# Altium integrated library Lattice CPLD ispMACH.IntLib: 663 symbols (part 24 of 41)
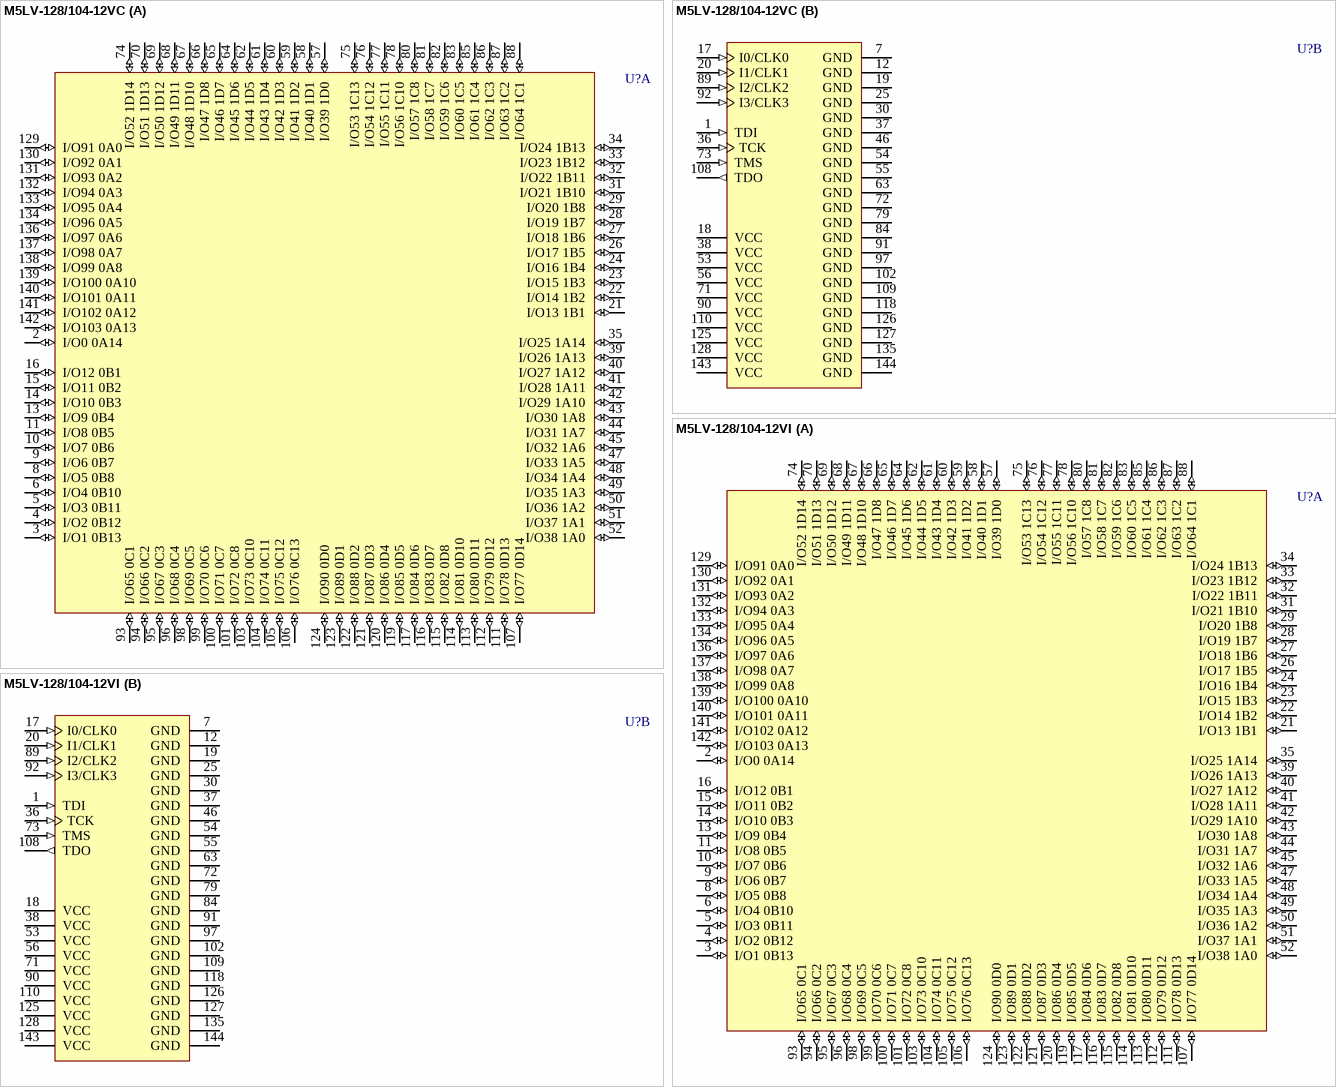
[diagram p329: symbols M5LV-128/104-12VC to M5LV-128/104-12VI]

## M5LV-128/104-12VI
designator U?
High-Density and High-I/O Complex PLD
footprint TQFP144_N (Thin QFP, 144-Leads, Body 20x20mm, Pitch 0.5mm, IPC Medium Density)
footprint TQFP144_L (Thin QFP, 144-Leads, Body 20x20mm, Pitch 0.5mm, IPC High Density)
footprint TQFP144_M (Thin QFP, 144-Leads, Body 20x20mm, Pitch 0.5mm, IPC Low Density)
3D model M5LV-TQFP144 (144-Pin Thin Quad Flat Pack (TQFP144))
part A pins: 2 I/O0 0A14 (io), 3 I/O1 0B13 (io), 4 I/O2 0B12 (io), 5 I/O3 0B11 (io), 6 I/O4 0B10 (io), 8 I/O5 0B8 (io), 9 I/O6 0B7 (io), 10 I/O7 0B6 (io), 11 I/O8 0B5 (io), 13 I/O9 0B4 (io), 14 I/O10 0B3 (io), 15 I/O11 0B2 (io), 16 I/O12 0B1 (io), 21 I/O13 1B1 (io), 22 I/O14 1B2 (io), 23 I/O15 1B3 (io), 24 I/O16 1B4 (io), 26 I/O17 1B5 (io), 27 I/O18 1B6 (io), 28 I/O19 1B7 (io), 29 I/O20 1B8 (io), 31 I/O21 1B10 (io), 32 I/O22 1B11 (io), 33 I/O23 1B12 (io), 34 I/O24 1B13 (io), 35 I/O25 1A14 (io), 39 I/O26 1A13 (io), 40 I/O27 1A12 (io), 41 I/O28 1A11 (io), 42 I/O29 1A10 (io), 43 I/O30 1A8 (io), 44 I/O31 1A7 (io), 45 I/O32 1A6 (io), 47 I/O33 1A5 (io), 48 I/O34 1A4 (io), 49 I/O35 1A3 (io), 50 I/O36 1A2 (io), 51 I/O37 1A1 (io), 52 I/O38 1A0 (io), 57 I/O39 1D0 (io), 58 I/O40 1D1 (io), 59 I/O41 1D2 (io), 60 I/O42 1D3 (io), 61 I/O43 1D4 (io), 62 I/O44 1D5 (io), 64 I/O45 1D6 (io), 65 I/O46 1D7 (io), 66 I/O47 1D8 (io), 67 I/O48 1D10 (io), 68 I/O49 1D11 (io), 69 I/O50 1D12 (io), 70 I/O51 1D13 (io), 74 I/O52 1D14 (io), 75 I/O53 1C13 (io), 76 I/O54 1C12 (io), 77 I/O55 1C11 (io), 78 I/O56 1C10 (io), 80 I/O57 1C8 (io), 81 I/O58 1C7 (io), 82 I/O59 1C6 (io), 83 I/O60 1C5 (io), 85 I/O61 1C4 (io), 86 I/O62 1C3 (io), 87 I/O63 1C2 (io), 88 I/O64 1C1 (io), 93 I/O65 0C1 (io), 94 I/O66 0C2 (io), 95 I/O67 0C3 (io), 96 I/O68 0C4 (io), 98 I/O69 0C5 (io), 99 I/O70 0C6 (io), 100 I/O71 0C7 (io), 101 I/O72 0C8 (io), 103 I/O73 0C10 (io), 104 I/O74 0C11 (io), 105 I/O75 0C12 (io), 106 I/O76 0C13 (io), 107 I/O77 0D14 (io), 111 I/O78 0D13 (io), 112 I/O79 0D12 (io), 113 I/O80 0D11 (io), 114 I/O81 0D10 (io), 115 I/O82 0D8 (io), 116 I/O83 0D7 (io), 117 I/O84 0D6 (io), 119 I/O85 0D5 (io), 120 I/O86 0D4 (io), 121 I/O87 0D3 (io), 122 I/O88 0D2 (io), 123 I/O89 0D1 (io), 124 I/O90 0D0 (io), 129 I/O91 0A0 (io), 130 I/O92 0A1 (io), 131 I/O93 0A2 (io), 132 I/O94 0A3 (io), 133 I/O95 0A4 (io), 134 I/O96 0A5 (io), 136 I/O97 0A6 (io), 137 I/O98 0A7 (io), 138 I/O99 0A8 (io), 139 I/O100 0A10 (io), 140 I/O101 0A11 (io), 141 I/O102 0A12 (io), 142 I/O103 0A13 (io)
part B pins: 1 TDI (in), 7 GND (power), 12 GND (power), 17 I0/CLK0 (in), 18 VCC (power), 19 GND (power), 20 I1/CLK1 (in), 25 GND (power), 30 GND (power), 36 TCK (in), 37 GND (power), 38 VCC (power), 46 GND (power), 53 VCC (power), 54 GND (power), 55 GND (power), 56 VCC (power), 63 GND (power), 71 VCC (power), 72 GND (power), 73 TMS (in), 79 GND (power), 84 GND (power), 89 I2/CLK2 (in), 90 VCC (power), 91 GND (power), 92 I3/CLK3 (in), 97 GND (power), 102 GND (power), 108 TDO (out), 109 GND (power), 110 VCC (power), 118 GND (power), 125 VCC (power), 126 GND (power), 127 GND (power), 128 VCC (power), 135 GND (power), 143 VCC (power), 144 GND (power)

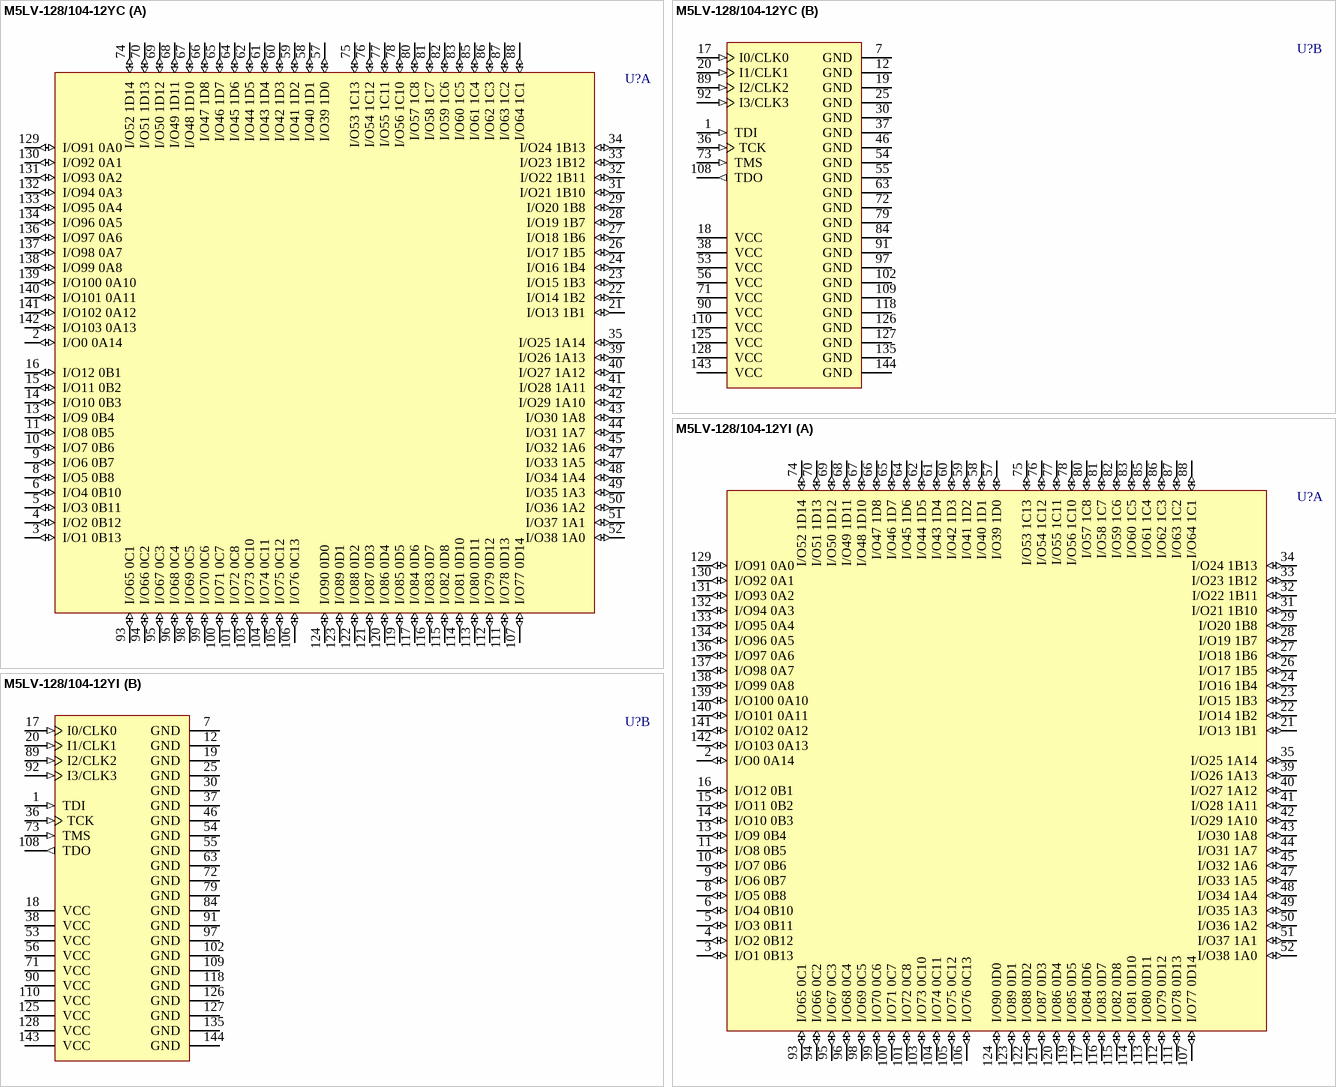
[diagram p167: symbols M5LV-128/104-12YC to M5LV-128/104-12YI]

## M5LV-128/104-12YC
designator U?
High-Density and High-I/O Complex PLD
footprint PQFP144_N (QFP, 144-Leads, Body 28 x 28mm, Pitch 0.65mm, IPC Medium Density)
footprint PQFP144_L (QFP, 144-Leads, Body 28 x 28mm, Pitch 0.65mm, IPC High Density)
footprint PQFP144_M (QFP, 144-Leads, Body 28 x 28mm, Pitch 0.65mm, IPC Low Density)
3D model M5LV-PQFP144 (144-Pin Quad Flat Pack 0.65 mm Pitch)
part A pins: 2 I/O0 0A14 (io), 3 I/O1 0B13 (io), 4 I/O2 0B12 (io), 5 I/O3 0B11 (io), 6 I/O4 0B10 (io), 8 I/O5 0B8 (io), 9 I/O6 0B7 (io), 10 I/O7 0B6 (io), 11 I/O8 0B5 (io), 13 I/O9 0B4 (io), 14 I/O10 0B3 (io), 15 I/O11 0B2 (io), 16 I/O12 0B1 (io), 21 I/O13 1B1 (io), 22 I/O14 1B2 (io), 23 I/O15 1B3 (io), 24 I/O16 1B4 (io), 26 I/O17 1B5 (io), 27 I/O18 1B6 (io), 28 I/O19 1B7 (io), 29 I/O20 1B8 (io), 31 I/O21 1B10 (io), 32 I/O22 1B11 (io), 33 I/O23 1B12 (io), 34 I/O24 1B13 (io), 35 I/O25 1A14 (io), 39 I/O26 1A13 (io), 40 I/O27 1A12 (io), 41 I/O28 1A11 (io), 42 I/O29 1A10 (io), 43 I/O30 1A8 (io), 44 I/O31 1A7 (io), 45 I/O32 1A6 (io), 47 I/O33 1A5 (io), 48 I/O34 1A4 (io), 49 I/O35 1A3 (io), 50 I/O36 1A2 (io), 51 I/O37 1A1 (io), 52 I/O38 1A0 (io), 57 I/O39 1D0 (io), 58 I/O40 1D1 (io), 59 I/O41 1D2 (io), 60 I/O42 1D3 (io), 61 I/O43 1D4 (io), 62 I/O44 1D5 (io), 64 I/O45 1D6 (io), 65 I/O46 1D7 (io), 66 I/O47 1D8 (io), 67 I/O48 1D10 (io), 68 I/O49 1D11 (io), 69 I/O50 1D12 (io), 70 I/O51 1D13 (io), 74 I/O52 1D14 (io), 75 I/O53 1C13 (io), 76 I/O54 1C12 (io), 77 I/O55 1C11 (io), 78 I/O56 1C10 (io), 80 I/O57 1C8 (io), 81 I/O58 1C7 (io), 82 I/O59 1C6 (io), 83 I/O60 1C5 (io), 85 I/O61 1C4 (io), 86 I/O62 1C3 (io), 87 I/O63 1C2 (io), 88 I/O64 1C1 (io), 93 I/O65 0C1 (io), 94 I/O66 0C2 (io), 95 I/O67 0C3 (io), 96 I/O68 0C4 (io), 98 I/O69 0C5 (io), 99 I/O70 0C6 (io), 100 I/O71 0C7 (io), 101 I/O72 0C8 (io), 103 I/O73 0C10 (io), 104 I/O74 0C11 (io), 105 I/O75 0C12 (io), 106 I/O76 0C13 (io), 107 I/O77 0D14 (io), 111 I/O78 0D13 (io), 112 I/O79 0D12 (io), 113 I/O80 0D11 (io), 114 I/O81 0D10 (io), 115 I/O82 0D8 (io), 116 I/O83 0D7 (io), 117 I/O84 0D6 (io), 119 I/O85 0D5 (io), 120 I/O86 0D4 (io), 121 I/O87 0D3 (io), 122 I/O88 0D2 (io), 123 I/O89 0D1 (io), 124 I/O90 0D0 (io), 129 I/O91 0A0 (io), 130 I/O92 0A1 (io), 131 I/O93 0A2 (io), 132 I/O94 0A3 (io), 133 I/O95 0A4 (io), 134 I/O96 0A5 (io), 136 I/O97 0A6 (io), 137 I/O98 0A7 (io), 138 I/O99 0A8 (io), 139 I/O100 0A10 (io), 140 I/O101 0A11 (io), 141 I/O102 0A12 (io), 142 I/O103 0A13 (io)
part B pins: 1 TDI (in), 7 GND (power), 12 GND (power), 17 I0/CLK0 (in), 18 VCC (power), 19 GND (power), 20 I1/CLK1 (in), 25 GND (power), 30 GND (power), 36 TCK (in), 37 GND (power), 38 VCC (power), 46 GND (power), 53 VCC (power), 54 GND (power), 55 GND (power), 56 VCC (power), 63 GND (power), 71 VCC (power), 72 GND (power), 73 TMS (in), 79 GND (power), 84 GND (power), 89 I2/CLK2 (in), 90 VCC (power), 91 GND (power), 92 I3/CLK3 (in), 97 GND (power), 102 GND (power), 108 TDO (out), 109 GND (power), 110 VCC (power), 118 GND (power), 125 VCC (power), 126 GND (power), 127 GND (power), 128 VCC (power), 135 GND (power), 143 VCC (power), 144 GND (power)

## M5LV-128/104-12YI
designator U?
High-Density and High-I/O Complex PLD
footprint PQFP144_N (QFP, 144-Leads, Body 28 x 28mm, Pitch 0.65mm, IPC Medium Density)
footprint PQFP144_L (QFP, 144-Leads, Body 28 x 28mm, Pitch 0.65mm, IPC High Density)
footprint PQFP144_M (QFP, 144-Leads, Body 28 x 28mm, Pitch 0.65mm, IPC Low Density)
3D model M5LV-PQFP144 (144-Pin Quad Flat Pack 0.65 mm Pitch)
part A pins: 2 I/O0 0A14 (io), 3 I/O1 0B13 (io), 4 I/O2 0B12 (io), 5 I/O3 0B11 (io), 6 I/O4 0B10 (io), 8 I/O5 0B8 (io), 9 I/O6 0B7 (io), 10 I/O7 0B6 (io), 11 I/O8 0B5 (io), 13 I/O9 0B4 (io), 14 I/O10 0B3 (io), 15 I/O11 0B2 (io), 16 I/O12 0B1 (io), 21 I/O13 1B1 (io), 22 I/O14 1B2 (io), 23 I/O15 1B3 (io), 24 I/O16 1B4 (io), 26 I/O17 1B5 (io), 27 I/O18 1B6 (io), 28 I/O19 1B7 (io), 29 I/O20 1B8 (io), 31 I/O21 1B10 (io), 32 I/O22 1B11 (io), 33 I/O23 1B12 (io), 34 I/O24 1B13 (io), 35 I/O25 1A14 (io), 39 I/O26 1A13 (io), 40 I/O27 1A12 (io), 41 I/O28 1A11 (io), 42 I/O29 1A10 (io), 43 I/O30 1A8 (io), 44 I/O31 1A7 (io), 45 I/O32 1A6 (io), 47 I/O33 1A5 (io), 48 I/O34 1A4 (io), 49 I/O35 1A3 (io), 50 I/O36 1A2 (io), 51 I/O37 1A1 (io), 52 I/O38 1A0 (io), 57 I/O39 1D0 (io), 58 I/O40 1D1 (io), 59 I/O41 1D2 (io), 60 I/O42 1D3 (io), 61 I/O43 1D4 (io), 62 I/O44 1D5 (io), 64 I/O45 1D6 (io), 65 I/O46 1D7 (io), 66 I/O47 1D8 (io), 67 I/O48 1D10 (io), 68 I/O49 1D11 (io), 69 I/O50 1D12 (io), 70 I/O51 1D13 (io), 74 I/O52 1D14 (io), 75 I/O53 1C13 (io), 76 I/O54 1C12 (io), 77 I/O55 1C11 (io), 78 I/O56 1C10 (io), 80 I/O57 1C8 (io), 81 I/O58 1C7 (io), 82 I/O59 1C6 (io), 83 I/O60 1C5 (io), 85 I/O61 1C4 (io), 86 I/O62 1C3 (io), 87 I/O63 1C2 (io), 88 I/O64 1C1 (io), 93 I/O65 0C1 (io), 94 I/O66 0C2 (io), 95 I/O67 0C3 (io), 96 I/O68 0C4 (io), 98 I/O69 0C5 (io), 99 I/O70 0C6 (io), 100 I/O71 0C7 (io), 101 I/O72 0C8 (io), 103 I/O73 0C10 (io), 104 I/O74 0C11 (io), 105 I/O75 0C12 (io), 106 I/O76 0C13 (io), 107 I/O77 0D14 (io), 111 I/O78 0D13 (io), 112 I/O79 0D12 (io), 113 I/O80 0D11 (io), 114 I/O81 0D10 (io), 115 I/O82 0D8 (io), 116 I/O83 0D7 (io), 117 I/O84 0D6 (io), 119 I/O85 0D5 (io), 120 I/O86 0D4 (io), 121 I/O87 0D3 (io), 122 I/O88 0D2 (io), 123 I/O89 0D1 (io), 124 I/O90 0D0 (io), 129 I/O91 0A0 (io), 130 I/O92 0A1 (io), 131 I/O93 0A2 (io), 132 I/O94 0A3 (io), 133 I/O95 0A4 (io), 134 I/O96 0A5 (io), 136 I/O97 0A6 (io), 137 I/O98 0A7 (io), 138 I/O99 0A8 (io), 139 I/O100 0A10 (io), 140 I/O101 0A11 (io), 141 I/O102 0A12 (io), 142 I/O103 0A13 (io)
part B pins: 1 TDI (in), 7 GND (power), 12 GND (power), 17 I0/CLK0 (in), 18 VCC (power), 19 GND (power), 20 I1/CLK1 (in), 25 GND (power), 30 GND (power), 36 TCK (in), 37 GND (power), 38 VCC (power), 46 GND (power), 53 VCC (power), 54 GND (power), 55 GND (power), 56 VCC (power), 63 GND (power), 71 VCC (power), 72 GND (power), 73 TMS (in), 79 GND (power), 84 GND (power), 89 I2/CLK2 (in), 90 VCC (power), 91 GND (power), 92 I3/CLK3 (in), 97 GND (power), 102 GND (power), 108 TDO (out), 109 GND (power), 110 VCC (power), 118 GND (power), 125 VCC (power), 126 GND (power), 127 GND (power), 128 VCC (power), 135 GND (power), 143 VCC (power), 144 GND (power)

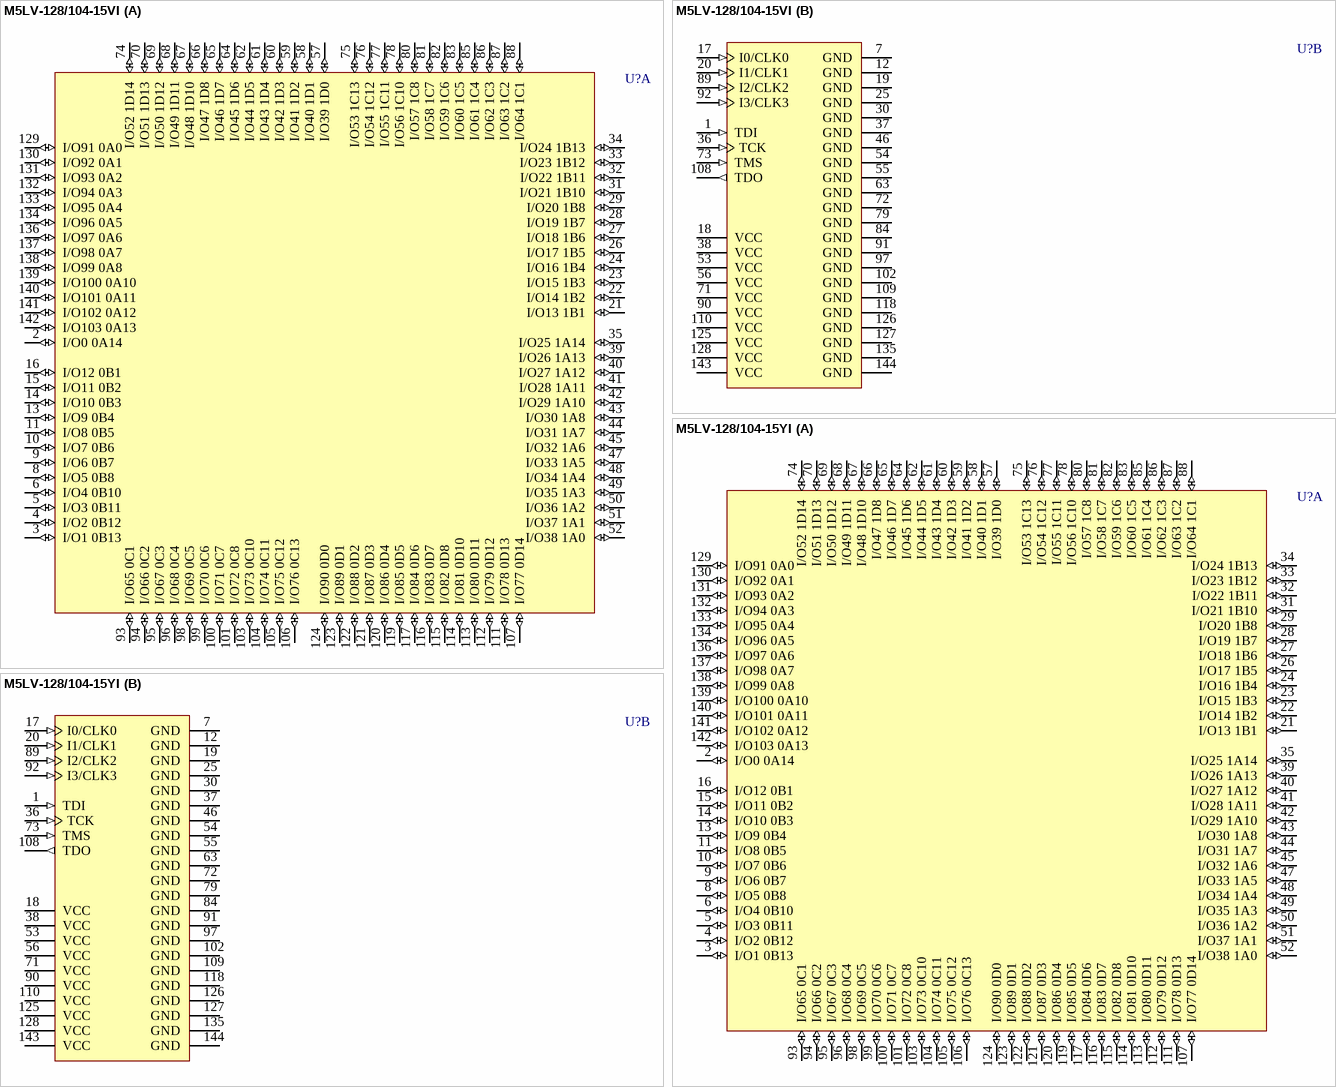
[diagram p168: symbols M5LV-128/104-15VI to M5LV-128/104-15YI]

## M5LV-128/104-15VI
designator U?
High-Density and High-I/O Complex PLD
footprint TQFP144_N (Thin QFP, 144-Leads, Body 20x20mm, Pitch 0.5mm, IPC Medium Density)
footprint TQFP144_L (Thin QFP, 144-Leads, Body 20x20mm, Pitch 0.5mm, IPC High Density)
footprint TQFP144_M (Thin QFP, 144-Leads, Body 20x20mm, Pitch 0.5mm, IPC Low Density)
3D model M5LV-TQFP144 (144-Pin Thin Quad Flat Pack (TQFP144))
part A pins: 2 I/O0 0A14 (io), 3 I/O1 0B13 (io), 4 I/O2 0B12 (io), 5 I/O3 0B11 (io), 6 I/O4 0B10 (io), 8 I/O5 0B8 (io), 9 I/O6 0B7 (io), 10 I/O7 0B6 (io), 11 I/O8 0B5 (io), 13 I/O9 0B4 (io), 14 I/O10 0B3 (io), 15 I/O11 0B2 (io), 16 I/O12 0B1 (io), 21 I/O13 1B1 (io), 22 I/O14 1B2 (io), 23 I/O15 1B3 (io), 24 I/O16 1B4 (io), 26 I/O17 1B5 (io), 27 I/O18 1B6 (io), 28 I/O19 1B7 (io), 29 I/O20 1B8 (io), 31 I/O21 1B10 (io), 32 I/O22 1B11 (io), 33 I/O23 1B12 (io), 34 I/O24 1B13 (io), 35 I/O25 1A14 (io), 39 I/O26 1A13 (io), 40 I/O27 1A12 (io), 41 I/O28 1A11 (io), 42 I/O29 1A10 (io), 43 I/O30 1A8 (io), 44 I/O31 1A7 (io), 45 I/O32 1A6 (io), 47 I/O33 1A5 (io), 48 I/O34 1A4 (io), 49 I/O35 1A3 (io), 50 I/O36 1A2 (io), 51 I/O37 1A1 (io), 52 I/O38 1A0 (io), 57 I/O39 1D0 (io), 58 I/O40 1D1 (io), 59 I/O41 1D2 (io), 60 I/O42 1D3 (io), 61 I/O43 1D4 (io), 62 I/O44 1D5 (io), 64 I/O45 1D6 (io), 65 I/O46 1D7 (io), 66 I/O47 1D8 (io), 67 I/O48 1D10 (io), 68 I/O49 1D11 (io), 69 I/O50 1D12 (io), 70 I/O51 1D13 (io), 74 I/O52 1D14 (io), 75 I/O53 1C13 (io), 76 I/O54 1C12 (io), 77 I/O55 1C11 (io), 78 I/O56 1C10 (io), 80 I/O57 1C8 (io), 81 I/O58 1C7 (io), 82 I/O59 1C6 (io), 83 I/O60 1C5 (io), 85 I/O61 1C4 (io), 86 I/O62 1C3 (io), 87 I/O63 1C2 (io), 88 I/O64 1C1 (io), 93 I/O65 0C1 (io), 94 I/O66 0C2 (io), 95 I/O67 0C3 (io), 96 I/O68 0C4 (io), 98 I/O69 0C5 (io), 99 I/O70 0C6 (io), 100 I/O71 0C7 (io), 101 I/O72 0C8 (io), 103 I/O73 0C10 (io), 104 I/O74 0C11 (io), 105 I/O75 0C12 (io), 106 I/O76 0C13 (io), 107 I/O77 0D14 (io), 111 I/O78 0D13 (io), 112 I/O79 0D12 (io), 113 I/O80 0D11 (io), 114 I/O81 0D10 (io), 115 I/O82 0D8 (io), 116 I/O83 0D7 (io), 117 I/O84 0D6 (io), 119 I/O85 0D5 (io), 120 I/O86 0D4 (io), 121 I/O87 0D3 (io), 122 I/O88 0D2 (io), 123 I/O89 0D1 (io), 124 I/O90 0D0 (io), 129 I/O91 0A0 (io), 130 I/O92 0A1 (io), 131 I/O93 0A2 (io), 132 I/O94 0A3 (io), 133 I/O95 0A4 (io), 134 I/O96 0A5 (io), 136 I/O97 0A6 (io), 137 I/O98 0A7 (io), 138 I/O99 0A8 (io), 139 I/O100 0A10 (io), 140 I/O101 0A11 (io), 141 I/O102 0A12 (io), 142 I/O103 0A13 (io)
part B pins: 1 TDI (in), 7 GND (power), 12 GND (power), 17 I0/CLK0 (in), 18 VCC (power), 19 GND (power), 20 I1/CLK1 (in), 25 GND (power), 30 GND (power), 36 TCK (in), 37 GND (power), 38 VCC (power), 46 GND (power), 53 VCC (power), 54 GND (power), 55 GND (power), 56 VCC (power), 63 GND (power), 71 VCC (power), 72 GND (power), 73 TMS (in), 79 GND (power), 84 GND (power), 89 I2/CLK2 (in), 90 VCC (power), 91 GND (power), 92 I3/CLK3 (in), 97 GND (power), 102 GND (power), 108 TDO (out), 109 GND (power), 110 VCC (power), 118 GND (power), 125 VCC (power), 126 GND (power), 127 GND (power), 128 VCC (power), 135 GND (power), 143 VCC (power), 144 GND (power)

## M5LV-128/104-15YI
designator U?
High-Density and High-I/O Complex PLD
footprint PQFP144_N (QFP, 144-Leads, Body 28 x 28mm, Pitch 0.65mm, IPC Medium Density)
footprint PQFP144_L (QFP, 144-Leads, Body 28 x 28mm, Pitch 0.65mm, IPC High Density)
footprint PQFP144_M (QFP, 144-Leads, Body 28 x 28mm, Pitch 0.65mm, IPC Low Density)
3D model M5LV-PQFP144 (144-Pin Quad Flat Pack 0.65 mm Pitch)
part A pins: 2 I/O0 0A14 (io), 3 I/O1 0B13 (io), 4 I/O2 0B12 (io), 5 I/O3 0B11 (io), 6 I/O4 0B10 (io), 8 I/O5 0B8 (io), 9 I/O6 0B7 (io), 10 I/O7 0B6 (io), 11 I/O8 0B5 (io), 13 I/O9 0B4 (io), 14 I/O10 0B3 (io), 15 I/O11 0B2 (io), 16 I/O12 0B1 (io), 21 I/O13 1B1 (io), 22 I/O14 1B2 (io), 23 I/O15 1B3 (io), 24 I/O16 1B4 (io), 26 I/O17 1B5 (io), 27 I/O18 1B6 (io), 28 I/O19 1B7 (io), 29 I/O20 1B8 (io), 31 I/O21 1B10 (io), 32 I/O22 1B11 (io), 33 I/O23 1B12 (io), 34 I/O24 1B13 (io), 35 I/O25 1A14 (io), 39 I/O26 1A13 (io), 40 I/O27 1A12 (io), 41 I/O28 1A11 (io), 42 I/O29 1A10 (io), 43 I/O30 1A8 (io), 44 I/O31 1A7 (io), 45 I/O32 1A6 (io), 47 I/O33 1A5 (io), 48 I/O34 1A4 (io), 49 I/O35 1A3 (io), 50 I/O36 1A2 (io), 51 I/O37 1A1 (io), 52 I/O38 1A0 (io), 57 I/O39 1D0 (io), 58 I/O40 1D1 (io), 59 I/O41 1D2 (io), 60 I/O42 1D3 (io), 61 I/O43 1D4 (io), 62 I/O44 1D5 (io), 64 I/O45 1D6 (io), 65 I/O46 1D7 (io), 66 I/O47 1D8 (io), 67 I/O48 1D10 (io), 68 I/O49 1D11 (io), 69 I/O50 1D12 (io), 70 I/O51 1D13 (io), 74 I/O52 1D14 (io), 75 I/O53 1C13 (io), 76 I/O54 1C12 (io), 77 I/O55 1C11 (io), 78 I/O56 1C10 (io), 80 I/O57 1C8 (io), 81 I/O58 1C7 (io), 82 I/O59 1C6 (io), 83 I/O60 1C5 (io), 85 I/O61 1C4 (io), 86 I/O62 1C3 (io), 87 I/O63 1C2 (io), 88 I/O64 1C1 (io), 93 I/O65 0C1 (io), 94 I/O66 0C2 (io), 95 I/O67 0C3 (io), 96 I/O68 0C4 (io), 98 I/O69 0C5 (io), 99 I/O70 0C6 (io), 100 I/O71 0C7 (io), 101 I/O72 0C8 (io), 103 I/O73 0C10 (io), 104 I/O74 0C11 (io), 105 I/O75 0C12 (io), 106 I/O76 0C13 (io), 107 I/O77 0D14 (io), 111 I/O78 0D13 (io), 112 I/O79 0D12 (io), 113 I/O80 0D11 (io), 114 I/O81 0D10 (io), 115 I/O82 0D8 (io), 116 I/O83 0D7 (io), 117 I/O84 0D6 (io), 119 I/O85 0D5 (io), 120 I/O86 0D4 (io), 121 I/O87 0D3 (io), 122 I/O88 0D2 (io), 123 I/O89 0D1 (io), 124 I/O90 0D0 (io), 129 I/O91 0A0 (io), 130 I/O92 0A1 (io), 131 I/O93 0A2 (io), 132 I/O94 0A3 (io), 133 I/O95 0A4 (io), 134 I/O96 0A5 (io), 136 I/O97 0A6 (io), 137 I/O98 0A7 (io), 138 I/O99 0A8 (io), 139 I/O100 0A10 (io), 140 I/O101 0A11 (io), 141 I/O102 0A12 (io), 142 I/O103 0A13 (io)
part B pins: 1 TDI (in), 7 GND (power), 12 GND (power), 17 I0/CLK0 (in), 18 VCC (power), 19 GND (power), 20 I1/CLK1 (in), 25 GND (power), 30 GND (power), 36 TCK (in), 37 GND (power), 38 VCC (power), 46 GND (power), 53 VCC (power), 54 GND (power), 55 GND (power), 56 VCC (power), 63 GND (power), 71 VCC (power), 72 GND (power), 73 TMS (in), 79 GND (power), 84 GND (power), 89 I2/CLK2 (in), 90 VCC (power), 91 GND (power), 92 I3/CLK3 (in), 97 GND (power), 102 GND (power), 108 TDO (out), 109 GND (power), 110 VCC (power), 118 GND (power), 125 VCC (power), 126 GND (power), 127 GND (power), 128 VCC (power), 135 GND (power), 143 VCC (power), 144 GND (power)

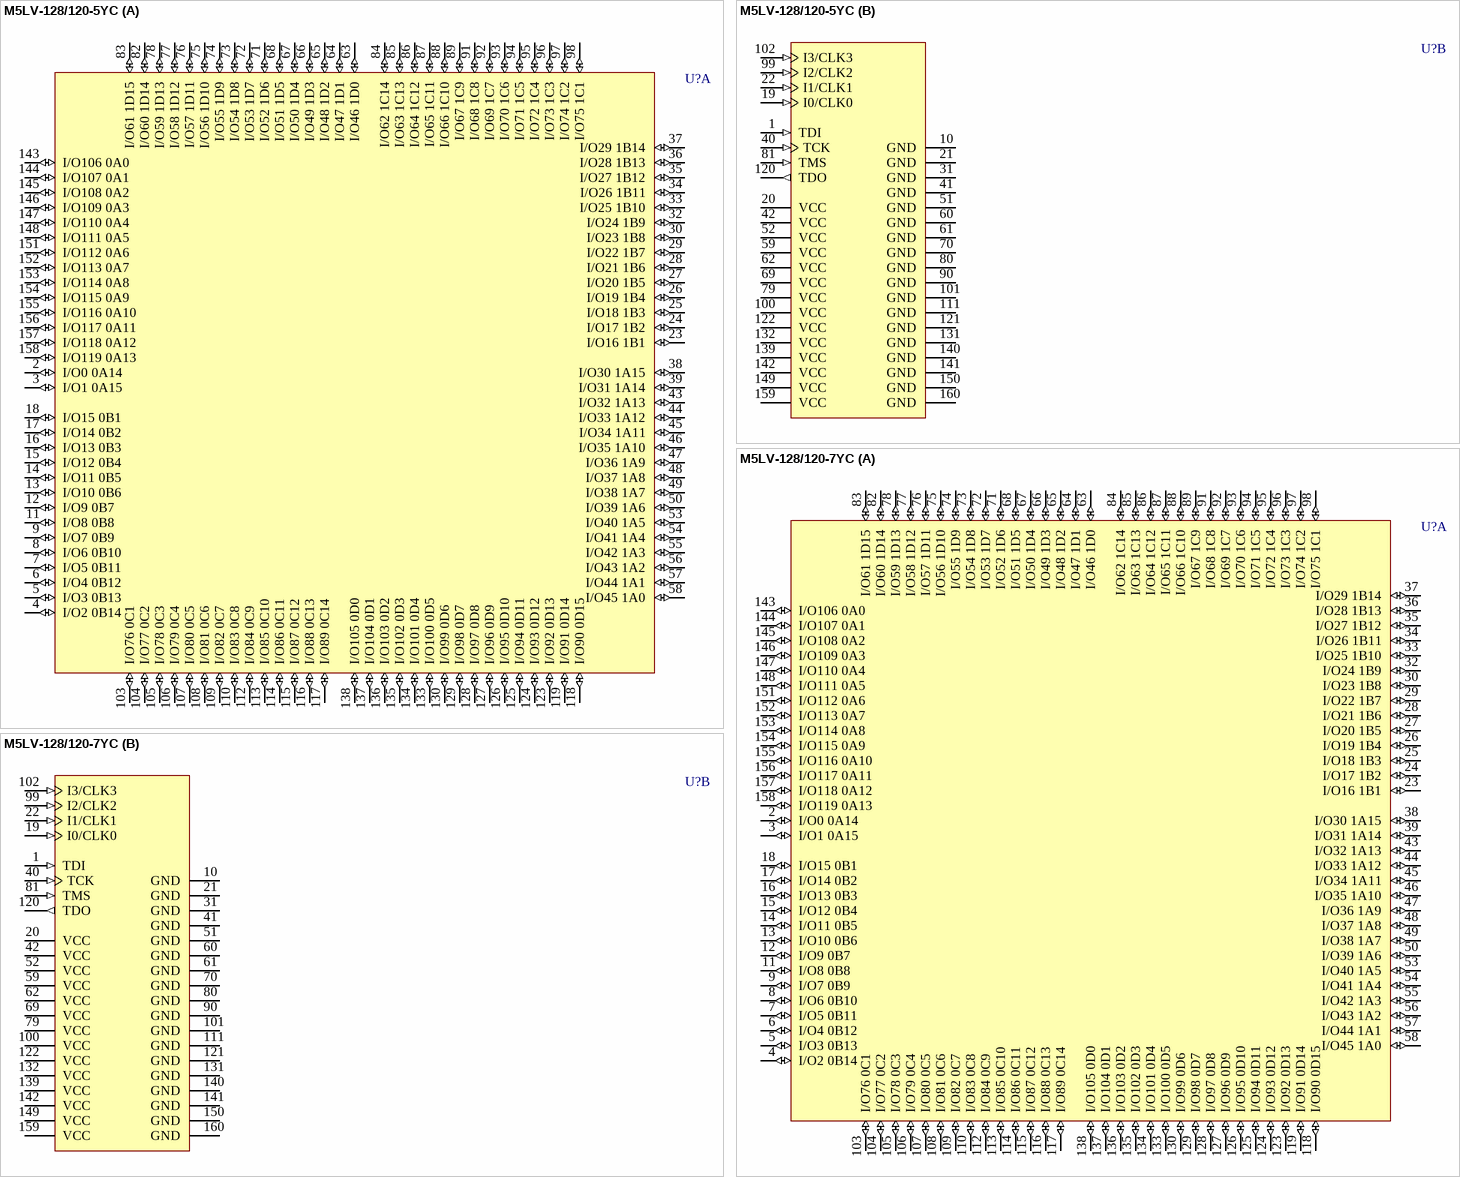
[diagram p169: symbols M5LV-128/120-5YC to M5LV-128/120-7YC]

## M5LV-128/120-5YC
designator U?
High-Density and High-I/O Complex PLD
footprint PQFP160_N (QFP, 160-Leads, Body 28 x 28mm, Pitch 0.65mm, IPC Medium Density)
footprint PQFP160_L (QFP, 160-Leads, Body 28 x 28mm, Pitch 0.65mm, IPC High Density)
footprint PQFP160_M (QFP, 160-Leads, Body 28 x 28mm, Pitch 0.65mm, IPC Low Density)
3D model M5LV-PQFP160 (160-Pin Quad Flat Pack 0.65 mm Pitch)
part A pins: 2 I/O0 0A14 (io), 3 I/O1 0A15 (io), 4 I/O2 0B14 (io), 5 I/O3 0B13 (io), 6 I/O4 0B12 (io), 7 I/O5 0B11 (io), 8 I/O6 0B10 (io), 9 I/O7 0B9 (io), 11 I/O8 0B8 (io), 12 I/O9 0B7 (io), 13 I/O10 0B6 (io), 14 I/O11 0B5 (io), 15 I/O12 0B4 (io), 16 I/O13 0B3 (io), 17 I/O14 0B2 (io), 18 I/O15 0B1 (io), 23 I/O16 1B1 (io), 24 I/O17 1B2 (io), 25 I/O18 1B3 (io), 26 I/O19 1B4 (io), 27 I/O20 1B5 (io), 28 I/O21 1B6 (io), 29 I/O22 1B7 (io), 30 I/O23 1B8 (io), 32 I/O24 1B9 (io), 33 I/O25 1B10 (io), 34 I/O26 1B11 (io), 35 I/O27 1B12 (io), 36 I/O28 1B13 (io), 37 I/O29 1B14 (io), 38 I/O30 1A15 (io), 39 I/O31 1A14 (io), 43 I/O32 1A13 (io), 44 I/O33 1A12 (io), 45 I/O34 1A11 (io), 46 I/O35 1A10 (io), 47 I/O36 1A9 (io), 48 I/O37 1A8 (io), 49 I/O38 1A7 (io), 50 I/O39 1A6 (io), 53 I/O40 1A5 (io), 54 I/O41 1A4 (io), 55 I/O42 1A3 (io), 56 I/O43 1A2 (io), 57 I/O44 1A1 (io), 58 I/O45 1A0 (io), 63 I/O46 1D0 (io), 64 I/O47 1D1 (io), 65 I/O48 1D2 (io), 66 I/O49 1D3 (io), 67 I/O50 1D4 (io), 68 I/O51 1D5 (io), 71 I/O52 1D6 (io), 72 I/O53 1D7 (io), 73 I/O54 1D8 (io), 74 I/O55 1D9 (io), 75 I/O56 1D10 (io), 76 I/O57 1D11 (io), 77 I/O58 1D12 (io), 78 I/O59 1D13 (io), 82 I/O60 1D14 (io), 83 I/O61 1D15 (io), 84 I/O62 1C14 (io), 85 I/O63 1C13 (io), 86 I/O64 1C12 (io), 87 I/O65 1C11 (io), 88 I/O66 1C10 (io), 89 I/O67 1C9 (io), 91 I/O68 1C8 (io), 92 I/O69 1C7 (io), 93 I/O70 1C6 (io), 94 I/O71 1C5 (io), 95 I/O72 1C4 (io), 96 I/O73 1C3 (io), 97 I/O74 1C2 (io), 98 I/O75 1C1 (io), 103 I/O76 0C1 (io), 104 I/O77 0C2 (io), 105 I/O78 0C3 (io), 106 I/O79 0C4 (io), 107 I/O80 0C5 (io), 108 I/O81 0C6 (io), 109 I/O82 0C7 (io), 110 I/O83 0C8 (io), 112 I/O84 0C9 (io), 113 I/O85 0C10 (io), 114 I/O86 0C11 (io), 115 I/O87 0C12 (io), 116 I/O88 0C13 (io), 117 I/O89 0C14 (io), 118 I/O90 0D15 (io), 119 I/O91 0D14 (io), 123 I/O92 0D13 (io), 124 I/O93 0D12 (io), 125 I/O94 0D11 (io), 126 I/O95 0D10 (io), 127 I/O96 0D9 (io), 128 I/O97 0D8 (io), 129 I/O98 0D7 (io), 130 I/O99 0D6 (io), 133 I/O100 0D5 (io), 134 I/O101 0D4 (io), 135 I/O102 0D3 (io), 136 I/O103 0D2 (io), 137 I/O104 0D1 (io), 138 I/O105 0D0 (io), 143 I/O106 0A0 (io), 144 I/O107 0A1 (io), 145 I/O108 0A2 (io), 146 I/O109 0A3 (io), 147 I/O110 0A4 (io), 148 I/O111 0A5 (io), 151 I/O112 0A6 (io), 152 I/O113 0A7 (io), 153 I/O114 0A8 (io), 154 I/O115 0A9 (io), 155 I/O116 0A10 (io), 156 I/O117 0A11 (io), 157 I/O118 0A12 (io), 158 I/O119 0A13 (io)
part B pins: 1 TDI (in), 10 GND (power), 19 I0/CLK0 (in), 20 VCC (power), 21 GND (power), 22 I1/CLK1 (in), 31 GND (power), 40 TCK (in), 41 GND (power), 42 VCC (power), 51 GND (power), 52 VCC (power), 59 VCC (power), 60 GND (power), 61 GND (power), 62 VCC (power), 69 VCC (power), 70 GND (power), 79 VCC (power), 80 GND (power), 81 TMS (in), 90 GND (power), 99 I2/CLK2 (in), 100 VCC (power), 101 GND (power), 102 I3/CLK3 (in), 111 GND (power), 120 TDO (out), 121 GND (power), 122 VCC (power), 131 GND (power), 132 VCC (power), 139 VCC (power), 140 GND (power), 141 GND (power), 142 VCC (power), 149 VCC (power), 150 GND (power), 159 VCC (power), 160 GND (power)

## M5LV-128/120-7YC
designator U?
High-Density and High-I/O Complex PLD
footprint PQFP160_N (QFP, 160-Leads, Body 28 x 28mm, Pitch 0.65mm, IPC Medium Density)
footprint PQFP160_L (QFP, 160-Leads, Body 28 x 28mm, Pitch 0.65mm, IPC High Density)
footprint PQFP160_M (QFP, 160-Leads, Body 28 x 28mm, Pitch 0.65mm, IPC Low Density)
3D model M5LV-PQFP160 (160-Pin Quad Flat Pack 0.65 mm Pitch)
part A pins: 2 I/O0 0A14 (io), 3 I/O1 0A15 (io), 4 I/O2 0B14 (io), 5 I/O3 0B13 (io), 6 I/O4 0B12 (io), 7 I/O5 0B11 (io), 8 I/O6 0B10 (io), 9 I/O7 0B9 (io), 11 I/O8 0B8 (io), 12 I/O9 0B7 (io), 13 I/O10 0B6 (io), 14 I/O11 0B5 (io), 15 I/O12 0B4 (io), 16 I/O13 0B3 (io), 17 I/O14 0B2 (io), 18 I/O15 0B1 (io), 23 I/O16 1B1 (io), 24 I/O17 1B2 (io), 25 I/O18 1B3 (io), 26 I/O19 1B4 (io), 27 I/O20 1B5 (io), 28 I/O21 1B6 (io), 29 I/O22 1B7 (io), 30 I/O23 1B8 (io), 32 I/O24 1B9 (io), 33 I/O25 1B10 (io), 34 I/O26 1B11 (io), 35 I/O27 1B12 (io), 36 I/O28 1B13 (io), 37 I/O29 1B14 (io), 38 I/O30 1A15 (io), 39 I/O31 1A14 (io), 43 I/O32 1A13 (io), 44 I/O33 1A12 (io), 45 I/O34 1A11 (io), 46 I/O35 1A10 (io), 47 I/O36 1A9 (io), 48 I/O37 1A8 (io), 49 I/O38 1A7 (io), 50 I/O39 1A6 (io), 53 I/O40 1A5 (io), 54 I/O41 1A4 (io), 55 I/O42 1A3 (io), 56 I/O43 1A2 (io), 57 I/O44 1A1 (io), 58 I/O45 1A0 (io), 63 I/O46 1D0 (io), 64 I/O47 1D1 (io), 65 I/O48 1D2 (io), 66 I/O49 1D3 (io), 67 I/O50 1D4 (io), 68 I/O51 1D5 (io), 71 I/O52 1D6 (io), 72 I/O53 1D7 (io), 73 I/O54 1D8 (io), 74 I/O55 1D9 (io), 75 I/O56 1D10 (io), 76 I/O57 1D11 (io), 77 I/O58 1D12 (io), 78 I/O59 1D13 (io), 82 I/O60 1D14 (io), 83 I/O61 1D15 (io), 84 I/O62 1C14 (io), 85 I/O63 1C13 (io), 86 I/O64 1C12 (io), 87 I/O65 1C11 (io), 88 I/O66 1C10 (io), 89 I/O67 1C9 (io), 91 I/O68 1C8 (io), 92 I/O69 1C7 (io), 93 I/O70 1C6 (io), 94 I/O71 1C5 (io), 95 I/O72 1C4 (io), 96 I/O73 1C3 (io), 97 I/O74 1C2 (io), 98 I/O75 1C1 (io), 103 I/O76 0C1 (io), 104 I/O77 0C2 (io), 105 I/O78 0C3 (io), 106 I/O79 0C4 (io), 107 I/O80 0C5 (io), 108 I/O81 0C6 (io), 109 I/O82 0C7 (io), 110 I/O83 0C8 (io), 112 I/O84 0C9 (io), 113 I/O85 0C10 (io), 114 I/O86 0C11 (io), 115 I/O87 0C12 (io), 116 I/O88 0C13 (io), 117 I/O89 0C14 (io), 118 I/O90 0D15 (io), 119 I/O91 0D14 (io), 123 I/O92 0D13 (io), 124 I/O93 0D12 (io), 125 I/O94 0D11 (io), 126 I/O95 0D10 (io), 127 I/O96 0D9 (io), 128 I/O97 0D8 (io), 129 I/O98 0D7 (io), 130 I/O99 0D6 (io), 133 I/O100 0D5 (io), 134 I/O101 0D4 (io), 135 I/O102 0D3 (io), 136 I/O103 0D2 (io), 137 I/O104 0D1 (io), 138 I/O105 0D0 (io), 143 I/O106 0A0 (io), 144 I/O107 0A1 (io), 145 I/O108 0A2 (io), 146 I/O109 0A3 (io), 147 I/O110 0A4 (io), 148 I/O111 0A5 (io), 151 I/O112 0A6 (io), 152 I/O113 0A7 (io), 153 I/O114 0A8 (io), 154 I/O115 0A9 (io), 155 I/O116 0A10 (io), 156 I/O117 0A11 (io), 157 I/O118 0A12 (io), 158 I/O119 0A13 (io)
part B pins: 1 TDI (in), 10 GND (power), 19 I0/CLK0 (in), 20 VCC (power), 21 GND (power), 22 I1/CLK1 (in), 31 GND (power), 40 TCK (in), 41 GND (power), 42 VCC (power), 51 GND (power), 52 VCC (power), 59 VCC (power), 60 GND (power), 61 GND (power), 62 VCC (power), 69 VCC (power), 70 GND (power), 79 VCC (power), 80 GND (power), 81 TMS (in), 90 GND (power), 99 I2/CLK2 (in), 100 VCC (power), 101 GND (power), 102 I3/CLK3 (in), 111 GND (power), 120 TDO (out), 121 GND (power), 122 VCC (power), 131 GND (power), 132 VCC (power), 139 VCC (power), 140 GND (power), 141 GND (power), 142 VCC (power), 149 VCC (power), 150 GND (power), 159 VCC (power), 160 GND (power)

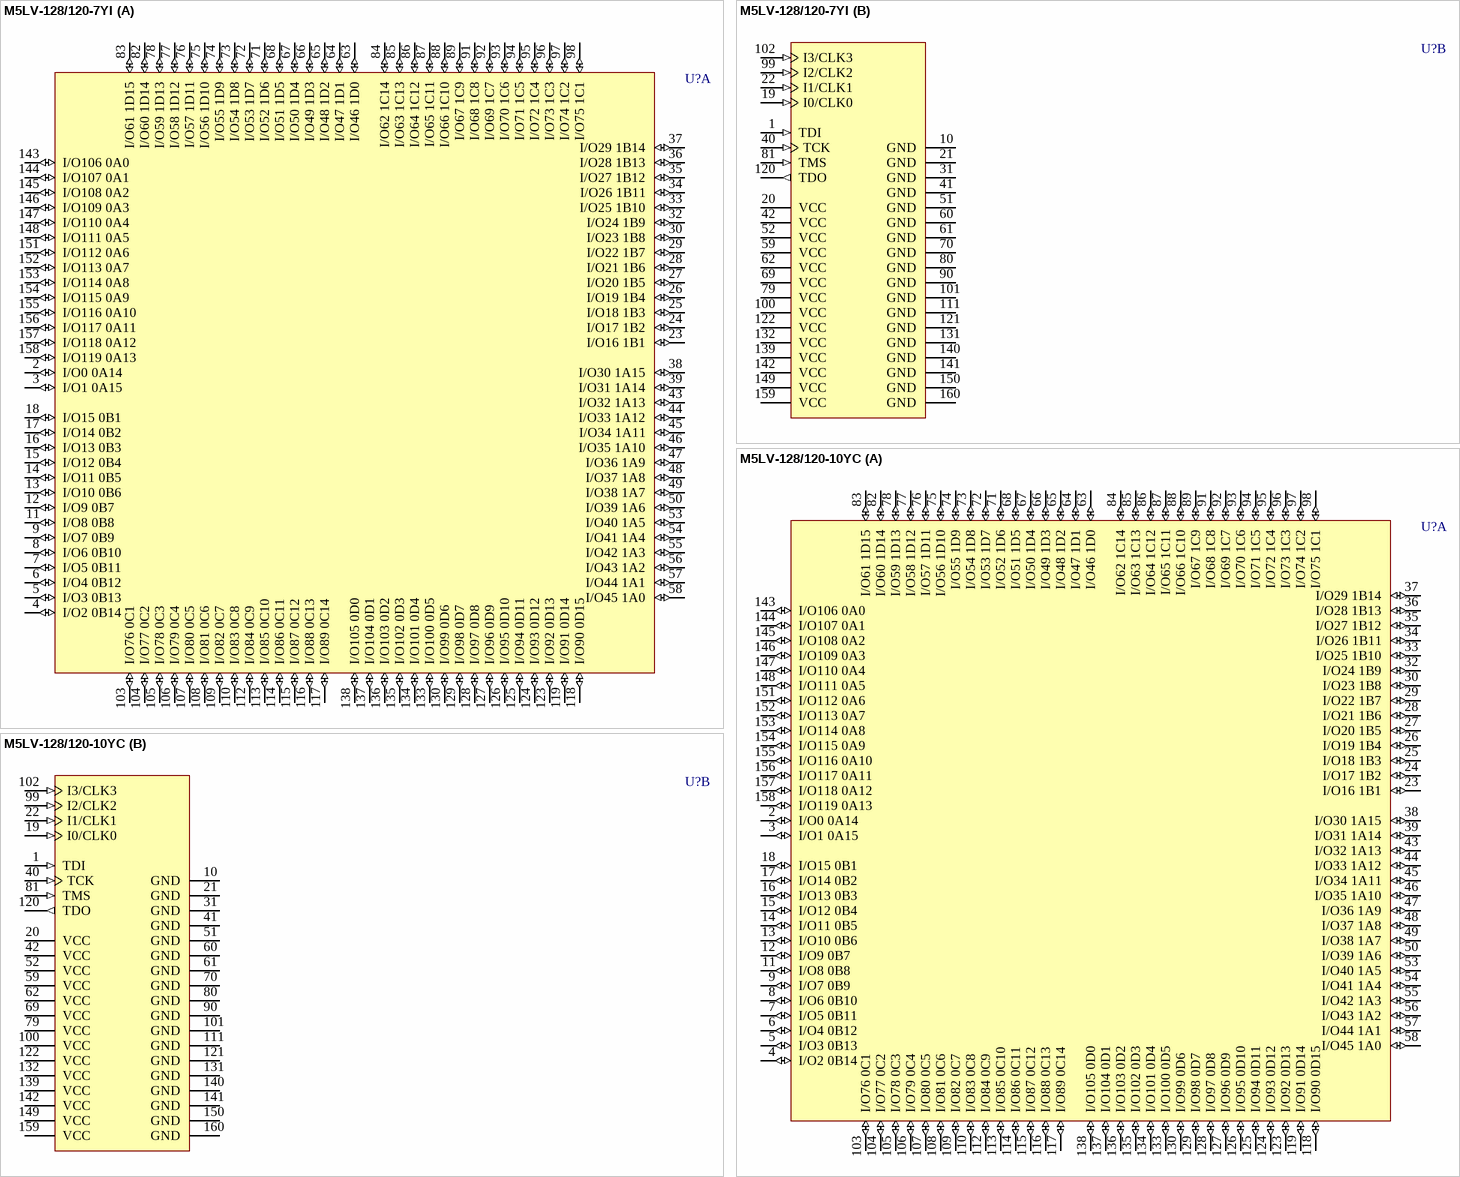
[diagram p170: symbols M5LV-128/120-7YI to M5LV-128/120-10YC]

## M5LV-128/120-7YI
designator U?
High-Density and High-I/O Complex PLD
footprint PQFP160_N (QFP, 160-Leads, Body 28 x 28mm, Pitch 0.65mm, IPC Medium Density)
footprint PQFP160_L (QFP, 160-Leads, Body 28 x 28mm, Pitch 0.65mm, IPC High Density)
footprint PQFP160_M (QFP, 160-Leads, Body 28 x 28mm, Pitch 0.65mm, IPC Low Density)
3D model M5LV-PQFP160 (160-Pin Quad Flat Pack 0.65 mm Pitch)
part A pins: 2 I/O0 0A14 (io), 3 I/O1 0A15 (io), 4 I/O2 0B14 (io), 5 I/O3 0B13 (io), 6 I/O4 0B12 (io), 7 I/O5 0B11 (io), 8 I/O6 0B10 (io), 9 I/O7 0B9 (io), 11 I/O8 0B8 (io), 12 I/O9 0B7 (io), 13 I/O10 0B6 (io), 14 I/O11 0B5 (io), 15 I/O12 0B4 (io), 16 I/O13 0B3 (io), 17 I/O14 0B2 (io), 18 I/O15 0B1 (io), 23 I/O16 1B1 (io), 24 I/O17 1B2 (io), 25 I/O18 1B3 (io), 26 I/O19 1B4 (io), 27 I/O20 1B5 (io), 28 I/O21 1B6 (io), 29 I/O22 1B7 (io), 30 I/O23 1B8 (io), 32 I/O24 1B9 (io), 33 I/O25 1B10 (io), 34 I/O26 1B11 (io), 35 I/O27 1B12 (io), 36 I/O28 1B13 (io), 37 I/O29 1B14 (io), 38 I/O30 1A15 (io), 39 I/O31 1A14 (io), 43 I/O32 1A13 (io), 44 I/O33 1A12 (io), 45 I/O34 1A11 (io), 46 I/O35 1A10 (io), 47 I/O36 1A9 (io), 48 I/O37 1A8 (io), 49 I/O38 1A7 (io), 50 I/O39 1A6 (io), 53 I/O40 1A5 (io), 54 I/O41 1A4 (io), 55 I/O42 1A3 (io), 56 I/O43 1A2 (io), 57 I/O44 1A1 (io), 58 I/O45 1A0 (io), 63 I/O46 1D0 (io), 64 I/O47 1D1 (io), 65 I/O48 1D2 (io), 66 I/O49 1D3 (io), 67 I/O50 1D4 (io), 68 I/O51 1D5 (io), 71 I/O52 1D6 (io), 72 I/O53 1D7 (io), 73 I/O54 1D8 (io), 74 I/O55 1D9 (io), 75 I/O56 1D10 (io), 76 I/O57 1D11 (io), 77 I/O58 1D12 (io), 78 I/O59 1D13 (io), 82 I/O60 1D14 (io), 83 I/O61 1D15 (io), 84 I/O62 1C14 (io), 85 I/O63 1C13 (io), 86 I/O64 1C12 (io), 87 I/O65 1C11 (io), 88 I/O66 1C10 (io), 89 I/O67 1C9 (io), 91 I/O68 1C8 (io), 92 I/O69 1C7 (io), 93 I/O70 1C6 (io), 94 I/O71 1C5 (io), 95 I/O72 1C4 (io), 96 I/O73 1C3 (io), 97 I/O74 1C2 (io), 98 I/O75 1C1 (io), 103 I/O76 0C1 (io), 104 I/O77 0C2 (io), 105 I/O78 0C3 (io), 106 I/O79 0C4 (io), 107 I/O80 0C5 (io), 108 I/O81 0C6 (io), 109 I/O82 0C7 (io), 110 I/O83 0C8 (io), 112 I/O84 0C9 (io), 113 I/O85 0C10 (io), 114 I/O86 0C11 (io), 115 I/O87 0C12 (io), 116 I/O88 0C13 (io), 117 I/O89 0C14 (io), 118 I/O90 0D15 (io), 119 I/O91 0D14 (io), 123 I/O92 0D13 (io), 124 I/O93 0D12 (io), 125 I/O94 0D11 (io), 126 I/O95 0D10 (io), 127 I/O96 0D9 (io), 128 I/O97 0D8 (io), 129 I/O98 0D7 (io), 130 I/O99 0D6 (io), 133 I/O100 0D5 (io), 134 I/O101 0D4 (io), 135 I/O102 0D3 (io), 136 I/O103 0D2 (io), 137 I/O104 0D1 (io), 138 I/O105 0D0 (io), 143 I/O106 0A0 (io), 144 I/O107 0A1 (io), 145 I/O108 0A2 (io), 146 I/O109 0A3 (io), 147 I/O110 0A4 (io), 148 I/O111 0A5 (io), 151 I/O112 0A6 (io), 152 I/O113 0A7 (io), 153 I/O114 0A8 (io), 154 I/O115 0A9 (io), 155 I/O116 0A10 (io), 156 I/O117 0A11 (io), 157 I/O118 0A12 (io), 158 I/O119 0A13 (io)
part B pins: 1 TDI (in), 10 GND (power), 19 I0/CLK0 (in), 20 VCC (power), 21 GND (power), 22 I1/CLK1 (in), 31 GND (power), 40 TCK (in), 41 GND (power), 42 VCC (power), 51 GND (power), 52 VCC (power), 59 VCC (power), 60 GND (power), 61 GND (power), 62 VCC (power), 69 VCC (power), 70 GND (power), 79 VCC (power), 80 GND (power), 81 TMS (in), 90 GND (power), 99 I2/CLK2 (in), 100 VCC (power), 101 GND (power), 102 I3/CLK3 (in), 111 GND (power), 120 TDO (out), 121 GND (power), 122 VCC (power), 131 GND (power), 132 VCC (power), 139 VCC (power), 140 GND (power), 141 GND (power), 142 VCC (power), 149 VCC (power), 150 GND (power), 159 VCC (power), 160 GND (power)

## M5LV-128/120-10YC
designator U?
High-Density and High-I/O Complex PLD
footprint PQFP160_N (QFP, 160-Leads, Body 28 x 28mm, Pitch 0.65mm, IPC Medium Density)
footprint PQFP160_L (QFP, 160-Leads, Body 28 x 28mm, Pitch 0.65mm, IPC High Density)
footprint PQFP160_M (QFP, 160-Leads, Body 28 x 28mm, Pitch 0.65mm, IPC Low Density)
3D model M5LV-PQFP160 (160-Pin Quad Flat Pack 0.65 mm Pitch)
part A pins: 2 I/O0 0A14 (io), 3 I/O1 0A15 (io), 4 I/O2 0B14 (io), 5 I/O3 0B13 (io), 6 I/O4 0B12 (io), 7 I/O5 0B11 (io), 8 I/O6 0B10 (io), 9 I/O7 0B9 (io), 11 I/O8 0B8 (io), 12 I/O9 0B7 (io), 13 I/O10 0B6 (io), 14 I/O11 0B5 (io), 15 I/O12 0B4 (io), 16 I/O13 0B3 (io), 17 I/O14 0B2 (io), 18 I/O15 0B1 (io), 23 I/O16 1B1 (io), 24 I/O17 1B2 (io), 25 I/O18 1B3 (io), 26 I/O19 1B4 (io), 27 I/O20 1B5 (io), 28 I/O21 1B6 (io), 29 I/O22 1B7 (io), 30 I/O23 1B8 (io), 32 I/O24 1B9 (io), 33 I/O25 1B10 (io), 34 I/O26 1B11 (io), 35 I/O27 1B12 (io), 36 I/O28 1B13 (io), 37 I/O29 1B14 (io), 38 I/O30 1A15 (io), 39 I/O31 1A14 (io), 43 I/O32 1A13 (io), 44 I/O33 1A12 (io), 45 I/O34 1A11 (io), 46 I/O35 1A10 (io), 47 I/O36 1A9 (io), 48 I/O37 1A8 (io), 49 I/O38 1A7 (io), 50 I/O39 1A6 (io), 53 I/O40 1A5 (io), 54 I/O41 1A4 (io), 55 I/O42 1A3 (io), 56 I/O43 1A2 (io), 57 I/O44 1A1 (io), 58 I/O45 1A0 (io), 63 I/O46 1D0 (io), 64 I/O47 1D1 (io), 65 I/O48 1D2 (io), 66 I/O49 1D3 (io), 67 I/O50 1D4 (io), 68 I/O51 1D5 (io), 71 I/O52 1D6 (io), 72 I/O53 1D7 (io), 73 I/O54 1D8 (io), 74 I/O55 1D9 (io), 75 I/O56 1D10 (io), 76 I/O57 1D11 (io), 77 I/O58 1D12 (io), 78 I/O59 1D13 (io), 82 I/O60 1D14 (io), 83 I/O61 1D15 (io), 84 I/O62 1C14 (io), 85 I/O63 1C13 (io), 86 I/O64 1C12 (io), 87 I/O65 1C11 (io), 88 I/O66 1C10 (io), 89 I/O67 1C9 (io), 91 I/O68 1C8 (io), 92 I/O69 1C7 (io), 93 I/O70 1C6 (io), 94 I/O71 1C5 (io), 95 I/O72 1C4 (io), 96 I/O73 1C3 (io), 97 I/O74 1C2 (io), 98 I/O75 1C1 (io), 103 I/O76 0C1 (io), 104 I/O77 0C2 (io), 105 I/O78 0C3 (io), 106 I/O79 0C4 (io), 107 I/O80 0C5 (io), 108 I/O81 0C6 (io), 109 I/O82 0C7 (io), 110 I/O83 0C8 (io), 112 I/O84 0C9 (io), 113 I/O85 0C10 (io), 114 I/O86 0C11 (io), 115 I/O87 0C12 (io), 116 I/O88 0C13 (io), 117 I/O89 0C14 (io), 118 I/O90 0D15 (io), 119 I/O91 0D14 (io), 123 I/O92 0D13 (io), 124 I/O93 0D12 (io), 125 I/O94 0D11 (io), 126 I/O95 0D10 (io), 127 I/O96 0D9 (io), 128 I/O97 0D8 (io), 129 I/O98 0D7 (io), 130 I/O99 0D6 (io), 133 I/O100 0D5 (io), 134 I/O101 0D4 (io), 135 I/O102 0D3 (io), 136 I/O103 0D2 (io), 137 I/O104 0D1 (io), 138 I/O105 0D0 (io), 143 I/O106 0A0 (io), 144 I/O107 0A1 (io), 145 I/O108 0A2 (io), 146 I/O109 0A3 (io), 147 I/O110 0A4 (io), 148 I/O111 0A5 (io), 151 I/O112 0A6 (io), 152 I/O113 0A7 (io), 153 I/O114 0A8 (io), 154 I/O115 0A9 (io), 155 I/O116 0A10 (io), 156 I/O117 0A11 (io), 157 I/O118 0A12 (io), 158 I/O119 0A13 (io)
part B pins: 1 TDI (in), 10 GND (power), 19 I0/CLK0 (in), 20 VCC (power), 21 GND (power), 22 I1/CLK1 (in), 31 GND (power), 40 TCK (in), 41 GND (power), 42 VCC (power), 51 GND (power), 52 VCC (power), 59 VCC (power), 60 GND (power), 61 GND (power), 62 VCC (power), 69 VCC (power), 70 GND (power), 79 VCC (power), 80 GND (power), 81 TMS (in), 90 GND (power), 99 I2/CLK2 (in), 100 VCC (power), 101 GND (power), 102 I3/CLK3 (in), 111 GND (power), 120 TDO (out), 121 GND (power), 122 VCC (power), 131 GND (power), 132 VCC (power), 139 VCC (power), 140 GND (power), 141 GND (power), 142 VCC (power), 149 VCC (power), 150 GND (power), 159 VCC (power), 160 GND (power)

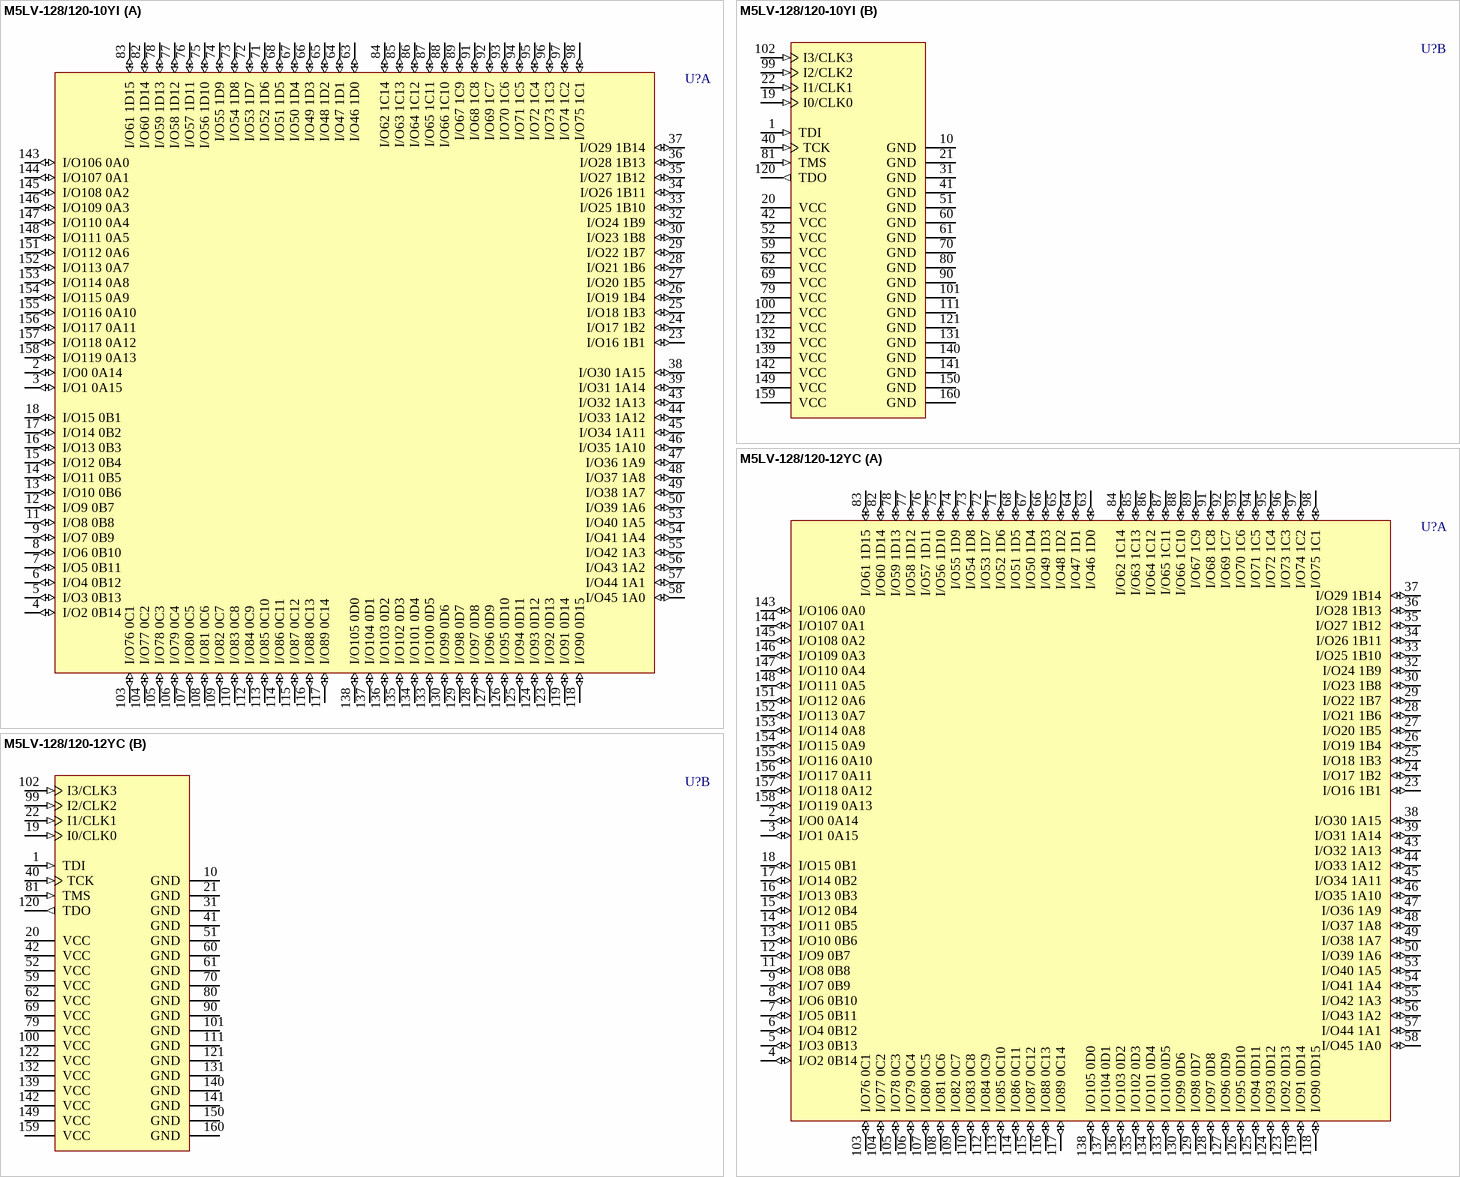
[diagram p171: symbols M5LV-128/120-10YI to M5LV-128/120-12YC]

## M5LV-128/120-10YI
designator U?
High-Density and High-I/O Complex PLD
footprint PQFP160_N (QFP, 160-Leads, Body 28 x 28mm, Pitch 0.65mm, IPC Medium Density)
footprint PQFP160_L (QFP, 160-Leads, Body 28 x 28mm, Pitch 0.65mm, IPC High Density)
footprint PQFP160_M (QFP, 160-Leads, Body 28 x 28mm, Pitch 0.65mm, IPC Low Density)
3D model M5LV-PQFP160 (160-Pin Quad Flat Pack 0.65 mm Pitch)
part A pins: 2 I/O0 0A14 (io), 3 I/O1 0A15 (io), 4 I/O2 0B14 (io), 5 I/O3 0B13 (io), 6 I/O4 0B12 (io), 7 I/O5 0B11 (io), 8 I/O6 0B10 (io), 9 I/O7 0B9 (io), 11 I/O8 0B8 (io), 12 I/O9 0B7 (io), 13 I/O10 0B6 (io), 14 I/O11 0B5 (io), 15 I/O12 0B4 (io), 16 I/O13 0B3 (io), 17 I/O14 0B2 (io), 18 I/O15 0B1 (io), 23 I/O16 1B1 (io), 24 I/O17 1B2 (io), 25 I/O18 1B3 (io), 26 I/O19 1B4 (io), 27 I/O20 1B5 (io), 28 I/O21 1B6 (io), 29 I/O22 1B7 (io), 30 I/O23 1B8 (io), 32 I/O24 1B9 (io), 33 I/O25 1B10 (io), 34 I/O26 1B11 (io), 35 I/O27 1B12 (io), 36 I/O28 1B13 (io), 37 I/O29 1B14 (io), 38 I/O30 1A15 (io), 39 I/O31 1A14 (io), 43 I/O32 1A13 (io), 44 I/O33 1A12 (io), 45 I/O34 1A11 (io), 46 I/O35 1A10 (io), 47 I/O36 1A9 (io), 48 I/O37 1A8 (io), 49 I/O38 1A7 (io), 50 I/O39 1A6 (io), 53 I/O40 1A5 (io), 54 I/O41 1A4 (io), 55 I/O42 1A3 (io), 56 I/O43 1A2 (io), 57 I/O44 1A1 (io), 58 I/O45 1A0 (io), 63 I/O46 1D0 (io), 64 I/O47 1D1 (io), 65 I/O48 1D2 (io), 66 I/O49 1D3 (io), 67 I/O50 1D4 (io), 68 I/O51 1D5 (io), 71 I/O52 1D6 (io), 72 I/O53 1D7 (io), 73 I/O54 1D8 (io), 74 I/O55 1D9 (io), 75 I/O56 1D10 (io), 76 I/O57 1D11 (io), 77 I/O58 1D12 (io), 78 I/O59 1D13 (io), 82 I/O60 1D14 (io), 83 I/O61 1D15 (io), 84 I/O62 1C14 (io), 85 I/O63 1C13 (io), 86 I/O64 1C12 (io), 87 I/O65 1C11 (io), 88 I/O66 1C10 (io), 89 I/O67 1C9 (io), 91 I/O68 1C8 (io), 92 I/O69 1C7 (io), 93 I/O70 1C6 (io), 94 I/O71 1C5 (io), 95 I/O72 1C4 (io), 96 I/O73 1C3 (io), 97 I/O74 1C2 (io), 98 I/O75 1C1 (io), 103 I/O76 0C1 (io), 104 I/O77 0C2 (io), 105 I/O78 0C3 (io), 106 I/O79 0C4 (io), 107 I/O80 0C5 (io), 108 I/O81 0C6 (io), 109 I/O82 0C7 (io), 110 I/O83 0C8 (io), 112 I/O84 0C9 (io), 113 I/O85 0C10 (io), 114 I/O86 0C11 (io), 115 I/O87 0C12 (io), 116 I/O88 0C13 (io), 117 I/O89 0C14 (io), 118 I/O90 0D15 (io), 119 I/O91 0D14 (io), 123 I/O92 0D13 (io), 124 I/O93 0D12 (io), 125 I/O94 0D11 (io), 126 I/O95 0D10 (io), 127 I/O96 0D9 (io), 128 I/O97 0D8 (io), 129 I/O98 0D7 (io), 130 I/O99 0D6 (io), 133 I/O100 0D5 (io), 134 I/O101 0D4 (io), 135 I/O102 0D3 (io), 136 I/O103 0D2 (io), 137 I/O104 0D1 (io), 138 I/O105 0D0 (io), 143 I/O106 0A0 (io), 144 I/O107 0A1 (io), 145 I/O108 0A2 (io), 146 I/O109 0A3 (io), 147 I/O110 0A4 (io), 148 I/O111 0A5 (io), 151 I/O112 0A6 (io), 152 I/O113 0A7 (io), 153 I/O114 0A8 (io), 154 I/O115 0A9 (io), 155 I/O116 0A10 (io), 156 I/O117 0A11 (io), 157 I/O118 0A12 (io), 158 I/O119 0A13 (io)
part B pins: 1 TDI (in), 10 GND (power), 19 I0/CLK0 (in), 20 VCC (power), 21 GND (power), 22 I1/CLK1 (in), 31 GND (power), 40 TCK (in), 41 GND (power), 42 VCC (power), 51 GND (power), 52 VCC (power), 59 VCC (power), 60 GND (power), 61 GND (power), 62 VCC (power), 69 VCC (power), 70 GND (power), 79 VCC (power), 80 GND (power), 81 TMS (in), 90 GND (power), 99 I2/CLK2 (in), 100 VCC (power), 101 GND (power), 102 I3/CLK3 (in), 111 GND (power), 120 TDO (out), 121 GND (power), 122 VCC (power), 131 GND (power), 132 VCC (power), 139 VCC (power), 140 GND (power), 141 GND (power), 142 VCC (power), 149 VCC (power), 150 GND (power), 159 VCC (power), 160 GND (power)

## M5LV-128/120-12YC
designator U?
High-Density and High-I/O Complex PLD
footprint PQFP160_N (QFP, 160-Leads, Body 28 x 28mm, Pitch 0.65mm, IPC Medium Density)
footprint PQFP160_L (QFP, 160-Leads, Body 28 x 28mm, Pitch 0.65mm, IPC High Density)
footprint PQFP160_M (QFP, 160-Leads, Body 28 x 28mm, Pitch 0.65mm, IPC Low Density)
3D model M5LV-PQFP160 (160-Pin Quad Flat Pack 0.65 mm Pitch)
part A pins: 2 I/O0 0A14 (io), 3 I/O1 0A15 (io), 4 I/O2 0B14 (io), 5 I/O3 0B13 (io), 6 I/O4 0B12 (io), 7 I/O5 0B11 (io), 8 I/O6 0B10 (io), 9 I/O7 0B9 (io), 11 I/O8 0B8 (io), 12 I/O9 0B7 (io), 13 I/O10 0B6 (io), 14 I/O11 0B5 (io), 15 I/O12 0B4 (io), 16 I/O13 0B3 (io), 17 I/O14 0B2 (io), 18 I/O15 0B1 (io), 23 I/O16 1B1 (io), 24 I/O17 1B2 (io), 25 I/O18 1B3 (io), 26 I/O19 1B4 (io), 27 I/O20 1B5 (io), 28 I/O21 1B6 (io), 29 I/O22 1B7 (io), 30 I/O23 1B8 (io), 32 I/O24 1B9 (io), 33 I/O25 1B10 (io), 34 I/O26 1B11 (io), 35 I/O27 1B12 (io), 36 I/O28 1B13 (io), 37 I/O29 1B14 (io), 38 I/O30 1A15 (io), 39 I/O31 1A14 (io), 43 I/O32 1A13 (io), 44 I/O33 1A12 (io), 45 I/O34 1A11 (io), 46 I/O35 1A10 (io), 47 I/O36 1A9 (io), 48 I/O37 1A8 (io), 49 I/O38 1A7 (io), 50 I/O39 1A6 (io), 53 I/O40 1A5 (io), 54 I/O41 1A4 (io), 55 I/O42 1A3 (io), 56 I/O43 1A2 (io), 57 I/O44 1A1 (io), 58 I/O45 1A0 (io), 63 I/O46 1D0 (io), 64 I/O47 1D1 (io), 65 I/O48 1D2 (io), 66 I/O49 1D3 (io), 67 I/O50 1D4 (io), 68 I/O51 1D5 (io), 71 I/O52 1D6 (io), 72 I/O53 1D7 (io), 73 I/O54 1D8 (io), 74 I/O55 1D9 (io), 75 I/O56 1D10 (io), 76 I/O57 1D11 (io), 77 I/O58 1D12 (io), 78 I/O59 1D13 (io), 82 I/O60 1D14 (io), 83 I/O61 1D15 (io), 84 I/O62 1C14 (io), 85 I/O63 1C13 (io), 86 I/O64 1C12 (io), 87 I/O65 1C11 (io), 88 I/O66 1C10 (io), 89 I/O67 1C9 (io), 91 I/O68 1C8 (io), 92 I/O69 1C7 (io), 93 I/O70 1C6 (io), 94 I/O71 1C5 (io), 95 I/O72 1C4 (io), 96 I/O73 1C3 (io), 97 I/O74 1C2 (io), 98 I/O75 1C1 (io), 103 I/O76 0C1 (io), 104 I/O77 0C2 (io), 105 I/O78 0C3 (io), 106 I/O79 0C4 (io), 107 I/O80 0C5 (io), 108 I/O81 0C6 (io), 109 I/O82 0C7 (io), 110 I/O83 0C8 (io), 112 I/O84 0C9 (io), 113 I/O85 0C10 (io), 114 I/O86 0C11 (io), 115 I/O87 0C12 (io), 116 I/O88 0C13 (io), 117 I/O89 0C14 (io), 118 I/O90 0D15 (io), 119 I/O91 0D14 (io), 123 I/O92 0D13 (io), 124 I/O93 0D12 (io), 125 I/O94 0D11 (io), 126 I/O95 0D10 (io), 127 I/O96 0D9 (io), 128 I/O97 0D8 (io), 129 I/O98 0D7 (io), 130 I/O99 0D6 (io), 133 I/O100 0D5 (io), 134 I/O101 0D4 (io), 135 I/O102 0D3 (io), 136 I/O103 0D2 (io), 137 I/O104 0D1 (io), 138 I/O105 0D0 (io), 143 I/O106 0A0 (io), 144 I/O107 0A1 (io), 145 I/O108 0A2 (io), 146 I/O109 0A3 (io), 147 I/O110 0A4 (io), 148 I/O111 0A5 (io), 151 I/O112 0A6 (io), 152 I/O113 0A7 (io), 153 I/O114 0A8 (io), 154 I/O115 0A9 (io), 155 I/O116 0A10 (io), 156 I/O117 0A11 (io), 157 I/O118 0A12 (io), 158 I/O119 0A13 (io)
part B pins: 1 TDI (in), 10 GND (power), 19 I0/CLK0 (in), 20 VCC (power), 21 GND (power), 22 I1/CLK1 (in), 31 GND (power), 40 TCK (in), 41 GND (power), 42 VCC (power), 51 GND (power), 52 VCC (power), 59 VCC (power), 60 GND (power), 61 GND (power), 62 VCC (power), 69 VCC (power), 70 GND (power), 79 VCC (power), 80 GND (power), 81 TMS (in), 90 GND (power), 99 I2/CLK2 (in), 100 VCC (power), 101 GND (power), 102 I3/CLK3 (in), 111 GND (power), 120 TDO (out), 121 GND (power), 122 VCC (power), 131 GND (power), 132 VCC (power), 139 VCC (power), 140 GND (power), 141 GND (power), 142 VCC (power), 149 VCC (power), 150 GND (power), 159 VCC (power), 160 GND (power)

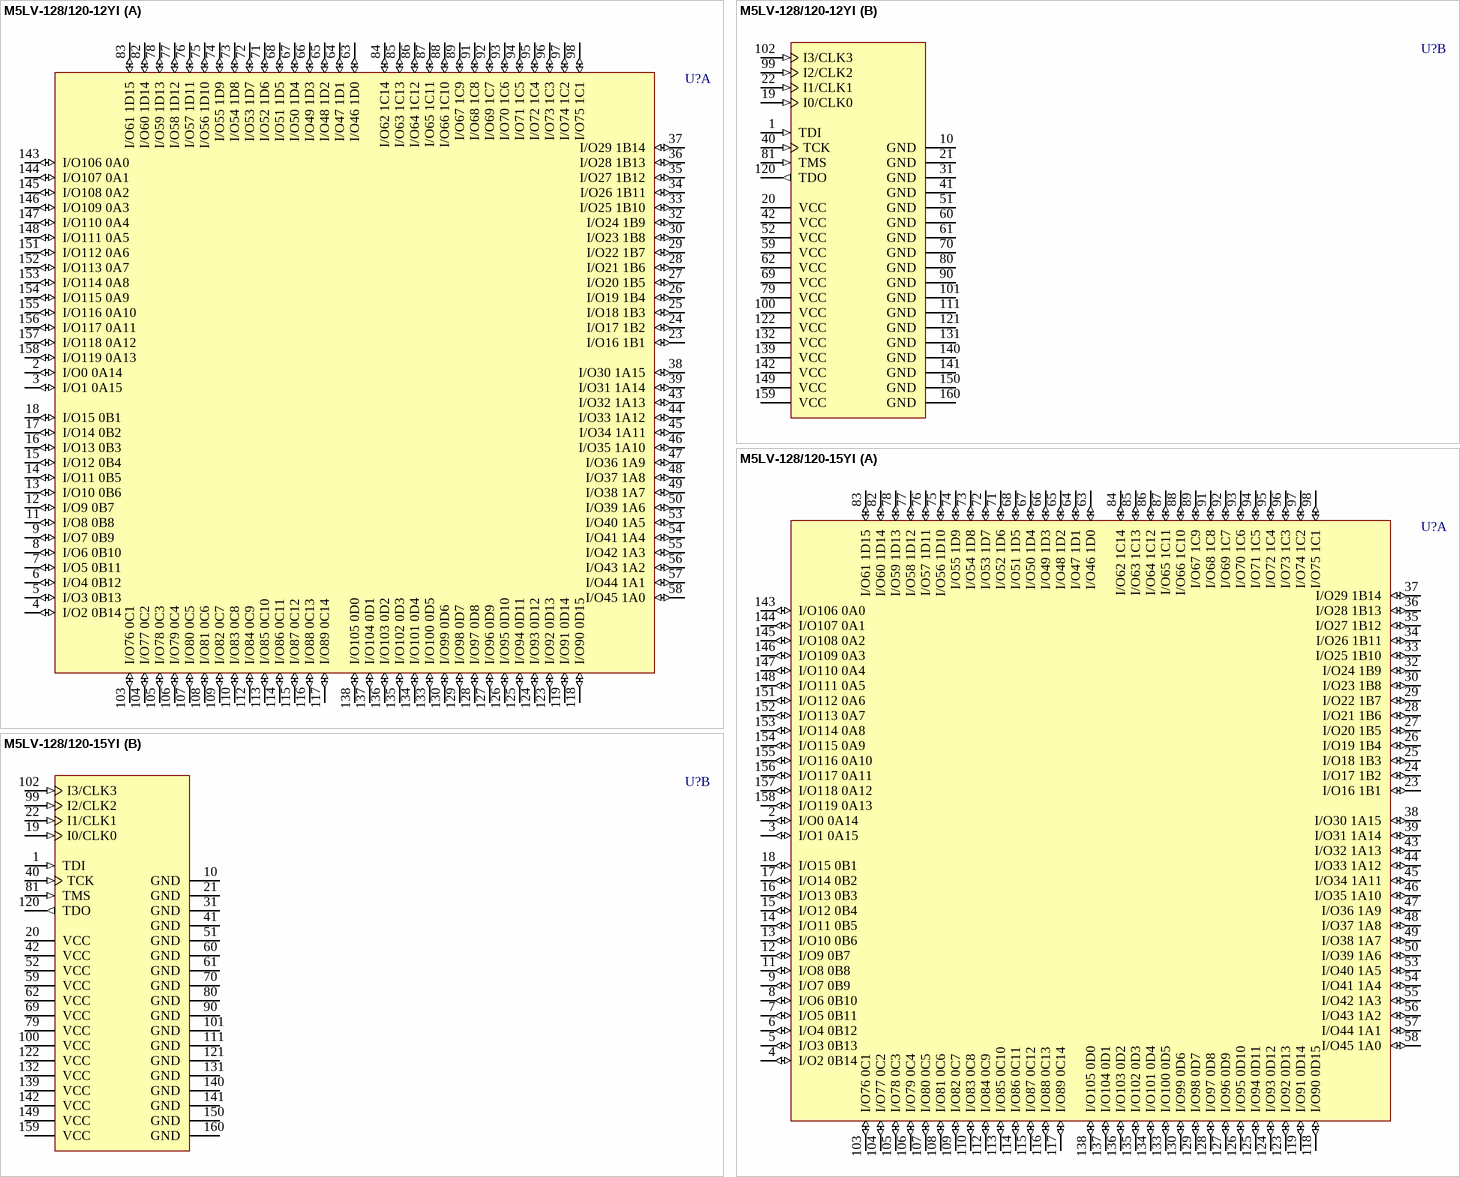
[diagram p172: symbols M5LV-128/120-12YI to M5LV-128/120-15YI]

## M5LV-128/120-12YI
designator U?
High-Density and High-I/O Complex PLD
footprint PQFP160_N (QFP, 160-Leads, Body 28 x 28mm, Pitch 0.65mm, IPC Medium Density)
footprint PQFP160_L (QFP, 160-Leads, Body 28 x 28mm, Pitch 0.65mm, IPC High Density)
footprint PQFP160_M (QFP, 160-Leads, Body 28 x 28mm, Pitch 0.65mm, IPC Low Density)
3D model M5LV-PQFP160 (160-Pin Quad Flat Pack 0.65 mm Pitch)
part A pins: 2 I/O0 0A14 (io), 3 I/O1 0A15 (io), 4 I/O2 0B14 (io), 5 I/O3 0B13 (io), 6 I/O4 0B12 (io), 7 I/O5 0B11 (io), 8 I/O6 0B10 (io), 9 I/O7 0B9 (io), 11 I/O8 0B8 (io), 12 I/O9 0B7 (io), 13 I/O10 0B6 (io), 14 I/O11 0B5 (io), 15 I/O12 0B4 (io), 16 I/O13 0B3 (io), 17 I/O14 0B2 (io), 18 I/O15 0B1 (io), 23 I/O16 1B1 (io), 24 I/O17 1B2 (io), 25 I/O18 1B3 (io), 26 I/O19 1B4 (io), 27 I/O20 1B5 (io), 28 I/O21 1B6 (io), 29 I/O22 1B7 (io), 30 I/O23 1B8 (io), 32 I/O24 1B9 (io), 33 I/O25 1B10 (io), 34 I/O26 1B11 (io), 35 I/O27 1B12 (io), 36 I/O28 1B13 (io), 37 I/O29 1B14 (io), 38 I/O30 1A15 (io), 39 I/O31 1A14 (io), 43 I/O32 1A13 (io), 44 I/O33 1A12 (io), 45 I/O34 1A11 (io), 46 I/O35 1A10 (io), 47 I/O36 1A9 (io), 48 I/O37 1A8 (io), 49 I/O38 1A7 (io), 50 I/O39 1A6 (io), 53 I/O40 1A5 (io), 54 I/O41 1A4 (io), 55 I/O42 1A3 (io), 56 I/O43 1A2 (io), 57 I/O44 1A1 (io), 58 I/O45 1A0 (io), 63 I/O46 1D0 (io), 64 I/O47 1D1 (io), 65 I/O48 1D2 (io), 66 I/O49 1D3 (io), 67 I/O50 1D4 (io), 68 I/O51 1D5 (io), 71 I/O52 1D6 (io), 72 I/O53 1D7 (io), 73 I/O54 1D8 (io), 74 I/O55 1D9 (io), 75 I/O56 1D10 (io), 76 I/O57 1D11 (io), 77 I/O58 1D12 (io), 78 I/O59 1D13 (io), 82 I/O60 1D14 (io), 83 I/O61 1D15 (io), 84 I/O62 1C14 (io), 85 I/O63 1C13 (io), 86 I/O64 1C12 (io), 87 I/O65 1C11 (io), 88 I/O66 1C10 (io), 89 I/O67 1C9 (io), 91 I/O68 1C8 (io), 92 I/O69 1C7 (io), 93 I/O70 1C6 (io), 94 I/O71 1C5 (io), 95 I/O72 1C4 (io), 96 I/O73 1C3 (io), 97 I/O74 1C2 (io), 98 I/O75 1C1 (io), 103 I/O76 0C1 (io), 104 I/O77 0C2 (io), 105 I/O78 0C3 (io), 106 I/O79 0C4 (io), 107 I/O80 0C5 (io), 108 I/O81 0C6 (io), 109 I/O82 0C7 (io), 110 I/O83 0C8 (io), 112 I/O84 0C9 (io), 113 I/O85 0C10 (io), 114 I/O86 0C11 (io), 115 I/O87 0C12 (io), 116 I/O88 0C13 (io), 117 I/O89 0C14 (io), 118 I/O90 0D15 (io), 119 I/O91 0D14 (io), 123 I/O92 0D13 (io), 124 I/O93 0D12 (io), 125 I/O94 0D11 (io), 126 I/O95 0D10 (io), 127 I/O96 0D9 (io), 128 I/O97 0D8 (io), 129 I/O98 0D7 (io), 130 I/O99 0D6 (io), 133 I/O100 0D5 (io), 134 I/O101 0D4 (io), 135 I/O102 0D3 (io), 136 I/O103 0D2 (io), 137 I/O104 0D1 (io), 138 I/O105 0D0 (io), 143 I/O106 0A0 (io), 144 I/O107 0A1 (io), 145 I/O108 0A2 (io), 146 I/O109 0A3 (io), 147 I/O110 0A4 (io), 148 I/O111 0A5 (io), 151 I/O112 0A6 (io), 152 I/O113 0A7 (io), 153 I/O114 0A8 (io), 154 I/O115 0A9 (io), 155 I/O116 0A10 (io), 156 I/O117 0A11 (io), 157 I/O118 0A12 (io), 158 I/O119 0A13 (io)
part B pins: 1 TDI (in), 10 GND (power), 19 I0/CLK0 (in), 20 VCC (power), 21 GND (power), 22 I1/CLK1 (in), 31 GND (power), 40 TCK (in), 41 GND (power), 42 VCC (power), 51 GND (power), 52 VCC (power), 59 VCC (power), 60 GND (power), 61 GND (power), 62 VCC (power), 69 VCC (power), 70 GND (power), 79 VCC (power), 80 GND (power), 81 TMS (in), 90 GND (power), 99 I2/CLK2 (in), 100 VCC (power), 101 GND (power), 102 I3/CLK3 (in), 111 GND (power), 120 TDO (out), 121 GND (power), 122 VCC (power), 131 GND (power), 132 VCC (power), 139 VCC (power), 140 GND (power), 141 GND (power), 142 VCC (power), 149 VCC (power), 150 GND (power), 159 VCC (power), 160 GND (power)

## M5LV-128/120-15YI
designator U?
High-Density and High-I/O Complex PLD
footprint PQFP160_N (QFP, 160-Leads, Body 28 x 28mm, Pitch 0.65mm, IPC Medium Density)
footprint PQFP160_L (QFP, 160-Leads, Body 28 x 28mm, Pitch 0.65mm, IPC High Density)
footprint PQFP160_M (QFP, 160-Leads, Body 28 x 28mm, Pitch 0.65mm, IPC Low Density)
3D model M5LV-PQFP160 (160-Pin Quad Flat Pack 0.65 mm Pitch)
part A pins: 2 I/O0 0A14 (io), 3 I/O1 0A15 (io), 4 I/O2 0B14 (io), 5 I/O3 0B13 (io), 6 I/O4 0B12 (io), 7 I/O5 0B11 (io), 8 I/O6 0B10 (io), 9 I/O7 0B9 (io), 11 I/O8 0B8 (io), 12 I/O9 0B7 (io), 13 I/O10 0B6 (io), 14 I/O11 0B5 (io), 15 I/O12 0B4 (io), 16 I/O13 0B3 (io), 17 I/O14 0B2 (io), 18 I/O15 0B1 (io), 23 I/O16 1B1 (io), 24 I/O17 1B2 (io), 25 I/O18 1B3 (io), 26 I/O19 1B4 (io), 27 I/O20 1B5 (io), 28 I/O21 1B6 (io), 29 I/O22 1B7 (io), 30 I/O23 1B8 (io), 32 I/O24 1B9 (io), 33 I/O25 1B10 (io), 34 I/O26 1B11 (io), 35 I/O27 1B12 (io), 36 I/O28 1B13 (io), 37 I/O29 1B14 (io), 38 I/O30 1A15 (io), 39 I/O31 1A14 (io), 43 I/O32 1A13 (io), 44 I/O33 1A12 (io), 45 I/O34 1A11 (io), 46 I/O35 1A10 (io), 47 I/O36 1A9 (io), 48 I/O37 1A8 (io), 49 I/O38 1A7 (io), 50 I/O39 1A6 (io), 53 I/O40 1A5 (io), 54 I/O41 1A4 (io), 55 I/O42 1A3 (io), 56 I/O43 1A2 (io), 57 I/O44 1A1 (io), 58 I/O45 1A0 (io), 63 I/O46 1D0 (io), 64 I/O47 1D1 (io), 65 I/O48 1D2 (io), 66 I/O49 1D3 (io), 67 I/O50 1D4 (io), 68 I/O51 1D5 (io), 71 I/O52 1D6 (io), 72 I/O53 1D7 (io), 73 I/O54 1D8 (io), 74 I/O55 1D9 (io), 75 I/O56 1D10 (io), 76 I/O57 1D11 (io), 77 I/O58 1D12 (io), 78 I/O59 1D13 (io), 82 I/O60 1D14 (io), 83 I/O61 1D15 (io), 84 I/O62 1C14 (io), 85 I/O63 1C13 (io), 86 I/O64 1C12 (io), 87 I/O65 1C11 (io), 88 I/O66 1C10 (io), 89 I/O67 1C9 (io), 91 I/O68 1C8 (io), 92 I/O69 1C7 (io), 93 I/O70 1C6 (io), 94 I/O71 1C5 (io), 95 I/O72 1C4 (io), 96 I/O73 1C3 (io), 97 I/O74 1C2 (io), 98 I/O75 1C1 (io), 103 I/O76 0C1 (io), 104 I/O77 0C2 (io), 105 I/O78 0C3 (io), 106 I/O79 0C4 (io), 107 I/O80 0C5 (io), 108 I/O81 0C6 (io), 109 I/O82 0C7 (io), 110 I/O83 0C8 (io), 112 I/O84 0C9 (io), 113 I/O85 0C10 (io), 114 I/O86 0C11 (io), 115 I/O87 0C12 (io), 116 I/O88 0C13 (io), 117 I/O89 0C14 (io), 118 I/O90 0D15 (io), 119 I/O91 0D14 (io), 123 I/O92 0D13 (io), 124 I/O93 0D12 (io), 125 I/O94 0D11 (io), 126 I/O95 0D10 (io), 127 I/O96 0D9 (io), 128 I/O97 0D8 (io), 129 I/O98 0D7 (io), 130 I/O99 0D6 (io), 133 I/O100 0D5 (io), 134 I/O101 0D4 (io), 135 I/O102 0D3 (io), 136 I/O103 0D2 (io), 137 I/O104 0D1 (io), 138 I/O105 0D0 (io), 143 I/O106 0A0 (io), 144 I/O107 0A1 (io), 145 I/O108 0A2 (io), 146 I/O109 0A3 (io), 147 I/O110 0A4 (io), 148 I/O111 0A5 (io), 151 I/O112 0A6 (io), 152 I/O113 0A7 (io), 153 I/O114 0A8 (io), 154 I/O115 0A9 (io), 155 I/O116 0A10 (io), 156 I/O117 0A11 (io), 157 I/O118 0A12 (io), 158 I/O119 0A13 (io)
part B pins: 1 TDI (in), 10 GND (power), 19 I0/CLK0 (in), 20 VCC (power), 21 GND (power), 22 I1/CLK1 (in), 31 GND (power), 40 TCK (in), 41 GND (power), 42 VCC (power), 51 GND (power), 52 VCC (power), 59 VCC (power), 60 GND (power), 61 GND (power), 62 VCC (power), 69 VCC (power), 70 GND (power), 79 VCC (power), 80 GND (power), 81 TMS (in), 90 GND (power), 99 I2/CLK2 (in), 100 VCC (power), 101 GND (power), 102 I3/CLK3 (in), 111 GND (power), 120 TDO (out), 121 GND (power), 122 VCC (power), 131 GND (power), 132 VCC (power), 139 VCC (power), 140 GND (power), 141 GND (power), 142 VCC (power), 149 VCC (power), 150 GND (power), 159 VCC (power), 160 GND (power)

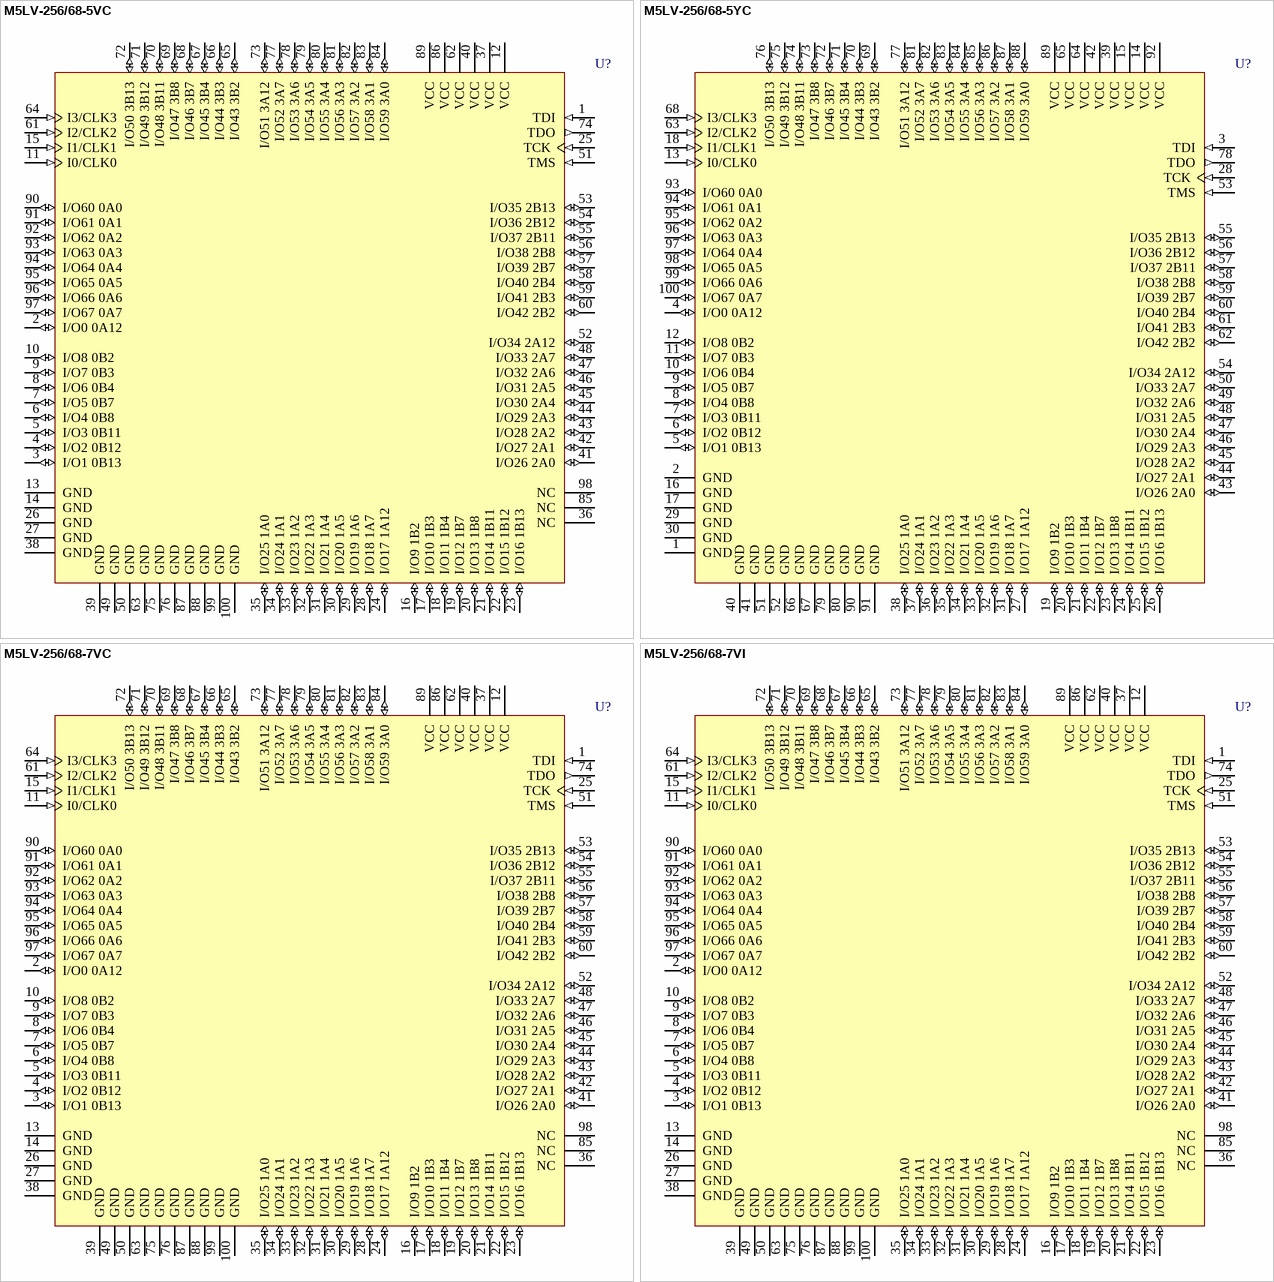
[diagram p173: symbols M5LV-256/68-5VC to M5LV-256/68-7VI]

## M5LV-256/68-5VC
designator U?
High-Density and High-I/O Complex PLD
footprint TQFP100_N (Thin QFP, 100-Leads, Body 14x14mm, Pitch 0.5mm, IPC Medium Density)
footprint TQFP100_L (Thin QFP, 100-Leads, Body 14x14mm, Pitch 0.5mm, IPC High Density)
footprint TQFP100_M (Thin QFP, 100-Leads, Body 14x14mm, Pitch 0.5mm, IPC Low Density)
3D model M5LV-TQFP100 (100-Pin Thin Quad Flat Pack (TQFP100))
pins: 1 TDI (in), 2 I/O0 0A12 (io), 3 I/O1 0B13 (io), 4 I/O2 0B12 (io), 5 I/O3 0B11 (io), 6 I/O4 0B8 (io), 7 I/O5 0B7 (io), 8 I/O6 0B4 (io), 9 I/O7 0B3 (io), 10 I/O8 0B2 (io), 11 I0/CLK0 (in), 12 VCC (power), 13 GND (power), 14 GND (power), 15 I1/CLK1 (in), 16 I/O9 1B2 (io), 17 I/O10 1B3 (io), 18 I/O11 1B4 (io), 19 I/O12 1B7 (io), 20 I/O13 1B8 (io), 21 I/O14 1B11 (io), 22 I/O15 1B12 (io), 23 I/O16 1B13 (io), 24 I/O17 1A12 (io), 25 TCK (in), 26 GND (power), 27 GND (power), 28 I/O18 1A7 (io), 29 I/O19 1A6 (io), 30 I/O20 1A5 (io), 31 I/O21 1A4 (io), 32 I/O22 1A3 (io), 33 I/O23 1A2 (io), 34 I/O24 1A1 (io), 35 I/O25 1A0 (io), 36 NC, 37 VCC (power), 38 GND (power), 39 GND (power), 40 VCC (power), 41 I/O26 2A0 (io), 42 I/O27 2A1 (io), 43 I/O28 2A2 (io), 44 I/O29 2A3 (io), 45 I/O30 2A4 (io), 46 I/O31 2A5 (io), 47 I/O32 2A6 (io), 48 I/O33 2A7 (io), 49 GND (power), 50 GND (power), 51 TMS (in), 52 I/O34 2A12 (io), 53 I/O35 2B13 (io), 54 I/O36 2B12 (io), 55 I/O37 2B11 (io), 56 I/O38 2B8 (io), 57 I/O39 2B7 (io), 58 I/O40 2B4 (io), 59 I/O41 2B3 (io), 60 I/O42 2B2 (io), 61 I2/CLK2 (in), 62 VCC (power), 63 GND (power), 64 I3/CLK3 (in), 65 I/O43 3B2 (io), 66 I/O44 3B3 (io), 67 I/O45 3B4 (io), 68 I/O46 3B7 (io), 69 I/O47 3B8 (io), 70 I/O48 3B11 (io), 71 I/O49 3B12 (io), 72 I/O50 3B13 (io), 73 I/O51 3A12 (io), 74 TDO (out), 75 GND (power), 76 GND (power), 77 I/O52 3A7 (io), 78 I/O53 3A6 (io), 79 I/O54 3A5 (io), 80 I/O55 3A4 (io), 81 I/O56 3A3 (io), 82 I/O57 3A2 (io), 83 I/O58 3A1 (io), 84 I/O59 3A0 (io), 85 NC, 86 VCC (power), 87 GND (power), 88 GND (power), 89 VCC (power), 90 I/O60 0A0 (io), 91 I/O61 0A1 (io), 92 I/O62 0A2 (io), 93 I/O63 0A3 (io), 94 I/O64 0A4 (io), 95 I/O65 0A5 (io), 96 I/O66 0A6 (io), 97 I/O67 0A7 (io), 98 NC, 99 GND (power), 100 GND (power)

## M5LV-256/68-5YC
designator U?
High-Density and High-I/O Complex PLD
footprint PQFP100_N (QFP, 100-Leads, Body 20x14mm, Pitch 0.65mm, IPC Medium Density)
footprint PQFP100_L (QFP, 100-Leads, Body 20x14mm, Pitch 0.65mm, IPC High Density)
footprint PQFP100_M (QFP, 100-Leads, Body 20x14mm, Pitch 0.65mm, IPC Low Density)
3D model PQFP-100 (100-Pin Quad Flat Pack Rectangular 0.65 mm Pitch)
pins: 1 GND (power), 2 GND (power), 3 TDI (in), 4 I/O0 0A12 (io), 5 I/O1 0B13 (io), 6 I/O2 0B12 (io), 7 I/O3 0B11 (io), 8 I/O4 0B8 (io), 9 I/O5 0B7 (io), 10 I/O6 0B4 (io), 11 I/O7 0B3 (io), 12 I/O8 0B2 (io), 13 I0/CLK0 (in), 14 VCC (power), 15 VCC (power), 16 GND (power), 17 GND (power), 18 I1/CLK1 (in), 19 I/O9 1B2 (io), 20 I/O10 1B3 (io), 21 I/O11 1B4 (io), 22 I/O12 1B7 (io), 23 I/O13 1B8 (io), 24 I/O14 1B11 (io), 25 I/O15 1B12 (io), 26 I/O16 1B13 (io), 27 I/O17 1A12 (io), 28 TCK (in), 29 GND (power), 30 GND (power), 31 I/O18 1A7 (io), 32 I/O19 1A6 (io), 33 I/O20 1A5 (io), 34 I/O21 1A4 (io), 35 I/O22 1A3 (io), 36 I/O23 1A2 (io), 37 I/O24 1A1 (io), 38 I/O25 1A0 (io), 39 VCC (power), 40 GND (power), 41 GND (power), 42 VCC (power), 43 I/O26 2A0 (io), 44 I/O27 2A1 (io), 45 I/O28 2A2 (io), 46 I/O29 2A3 (io), 47 I/O30 2A4 (io), 48 I/O31 2A5 (io), 49 I/O32 2A6 (io), 50 I/O33 2A7 (io), 51 GND (power), 52 GND (power), 53 TMS (in), 54 I/O34 2A12 (io), 55 I/O35 2B13 (io), 56 I/O36 2B12 (io), 57 I/O37 2B11 (io), 58 I/O38 2B8 (io), 59 I/O39 2B7 (io), 60 I/O40 2B4 (io), 61 I/O41 2B3 (io), 62 I/O42 2B2 (io), 63 I2/CLK2 (in), 64 VCC (power), 65 VCC (power), 66 GND (power), 67 GND (power), 68 I3/CLK3 (in), 69 I/O43 3B2 (io), 70 I/O44 3B3 (io), 71 I/O45 3B4 (io), 72 I/O46 3B7 (io), 73 I/O47 3B8 (io), 74 I/O48 3B11 (io), 75 I/O49 3B12 (io), 76 I/O50 3B13 (io), 77 I/O51 3A12 (io), 78 TDO (out), 79 GND (power), 80 GND (power), 81 I/O52 3A7 (io), 82 I/O53 3A6 (io), 83 I/O54 3A5 (io), 84 I/O55 3A4 (io), 85 I/O56 3A3 (io), 86 I/O57 3A2 (io), 87 I/O58 3A1 (io), 88 I/O59 3A0 (io), 89 VCC (power), 90 GND (power), 91 GND (power), 92 VCC (power), 93 I/O60 0A0 (io), 94 I/O61 0A1 (io), 95 I/O62 0A2 (io), 96 I/O63 0A3 (io), 97 I/O64 0A4 (io), 98 I/O65 0A5 (io), 99 I/O66 0A6 (io), 100 I/O67 0A7 (io)

## M5LV-256/68-7VC
designator U?
High-Density and High-I/O Complex PLD
footprint TQFP100_N (Thin QFP, 100-Leads, Body 14x14mm, Pitch 0.5mm, IPC Medium Density)
footprint TQFP100_L (Thin QFP, 100-Leads, Body 14x14mm, Pitch 0.5mm, IPC High Density)
footprint TQFP100_M (Thin QFP, 100-Leads, Body 14x14mm, Pitch 0.5mm, IPC Low Density)
3D model M5LV-TQFP100 (100-Pin Thin Quad Flat Pack (TQFP100))
pins: 1 TDI (in), 2 I/O0 0A12 (io), 3 I/O1 0B13 (io), 4 I/O2 0B12 (io), 5 I/O3 0B11 (io), 6 I/O4 0B8 (io), 7 I/O5 0B7 (io), 8 I/O6 0B4 (io), 9 I/O7 0B3 (io), 10 I/O8 0B2 (io), 11 I0/CLK0 (in), 12 VCC (power), 13 GND (power), 14 GND (power), 15 I1/CLK1 (in), 16 I/O9 1B2 (io), 17 I/O10 1B3 (io), 18 I/O11 1B4 (io), 19 I/O12 1B7 (io), 20 I/O13 1B8 (io), 21 I/O14 1B11 (io), 22 I/O15 1B12 (io), 23 I/O16 1B13 (io), 24 I/O17 1A12 (io), 25 TCK (in), 26 GND (power), 27 GND (power), 28 I/O18 1A7 (io), 29 I/O19 1A6 (io), 30 I/O20 1A5 (io), 31 I/O21 1A4 (io), 32 I/O22 1A3 (io), 33 I/O23 1A2 (io), 34 I/O24 1A1 (io), 35 I/O25 1A0 (io), 36 NC, 37 VCC (power), 38 GND (power), 39 GND (power), 40 VCC (power), 41 I/O26 2A0 (io), 42 I/O27 2A1 (io), 43 I/O28 2A2 (io), 44 I/O29 2A3 (io), 45 I/O30 2A4 (io), 46 I/O31 2A5 (io), 47 I/O32 2A6 (io), 48 I/O33 2A7 (io), 49 GND (power), 50 GND (power), 51 TMS (in), 52 I/O34 2A12 (io), 53 I/O35 2B13 (io), 54 I/O36 2B12 (io), 55 I/O37 2B11 (io), 56 I/O38 2B8 (io), 57 I/O39 2B7 (io), 58 I/O40 2B4 (io), 59 I/O41 2B3 (io), 60 I/O42 2B2 (io), 61 I2/CLK2 (in), 62 VCC (power), 63 GND (power), 64 I3/CLK3 (in), 65 I/O43 3B2 (io), 66 I/O44 3B3 (io), 67 I/O45 3B4 (io), 68 I/O46 3B7 (io), 69 I/O47 3B8 (io), 70 I/O48 3B11 (io), 71 I/O49 3B12 (io), 72 I/O50 3B13 (io), 73 I/O51 3A12 (io), 74 TDO (out), 75 GND (power), 76 GND (power), 77 I/O52 3A7 (io), 78 I/O53 3A6 (io), 79 I/O54 3A5 (io), 80 I/O55 3A4 (io), 81 I/O56 3A3 (io), 82 I/O57 3A2 (io), 83 I/O58 3A1 (io), 84 I/O59 3A0 (io), 85 NC, 86 VCC (power), 87 GND (power), 88 GND (power), 89 VCC (power), 90 I/O60 0A0 (io), 91 I/O61 0A1 (io), 92 I/O62 0A2 (io), 93 I/O63 0A3 (io), 94 I/O64 0A4 (io), 95 I/O65 0A5 (io), 96 I/O66 0A6 (io), 97 I/O67 0A7 (io), 98 NC, 99 GND (power), 100 GND (power)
